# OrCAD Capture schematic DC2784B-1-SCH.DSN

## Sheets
1 PAGE6: size C
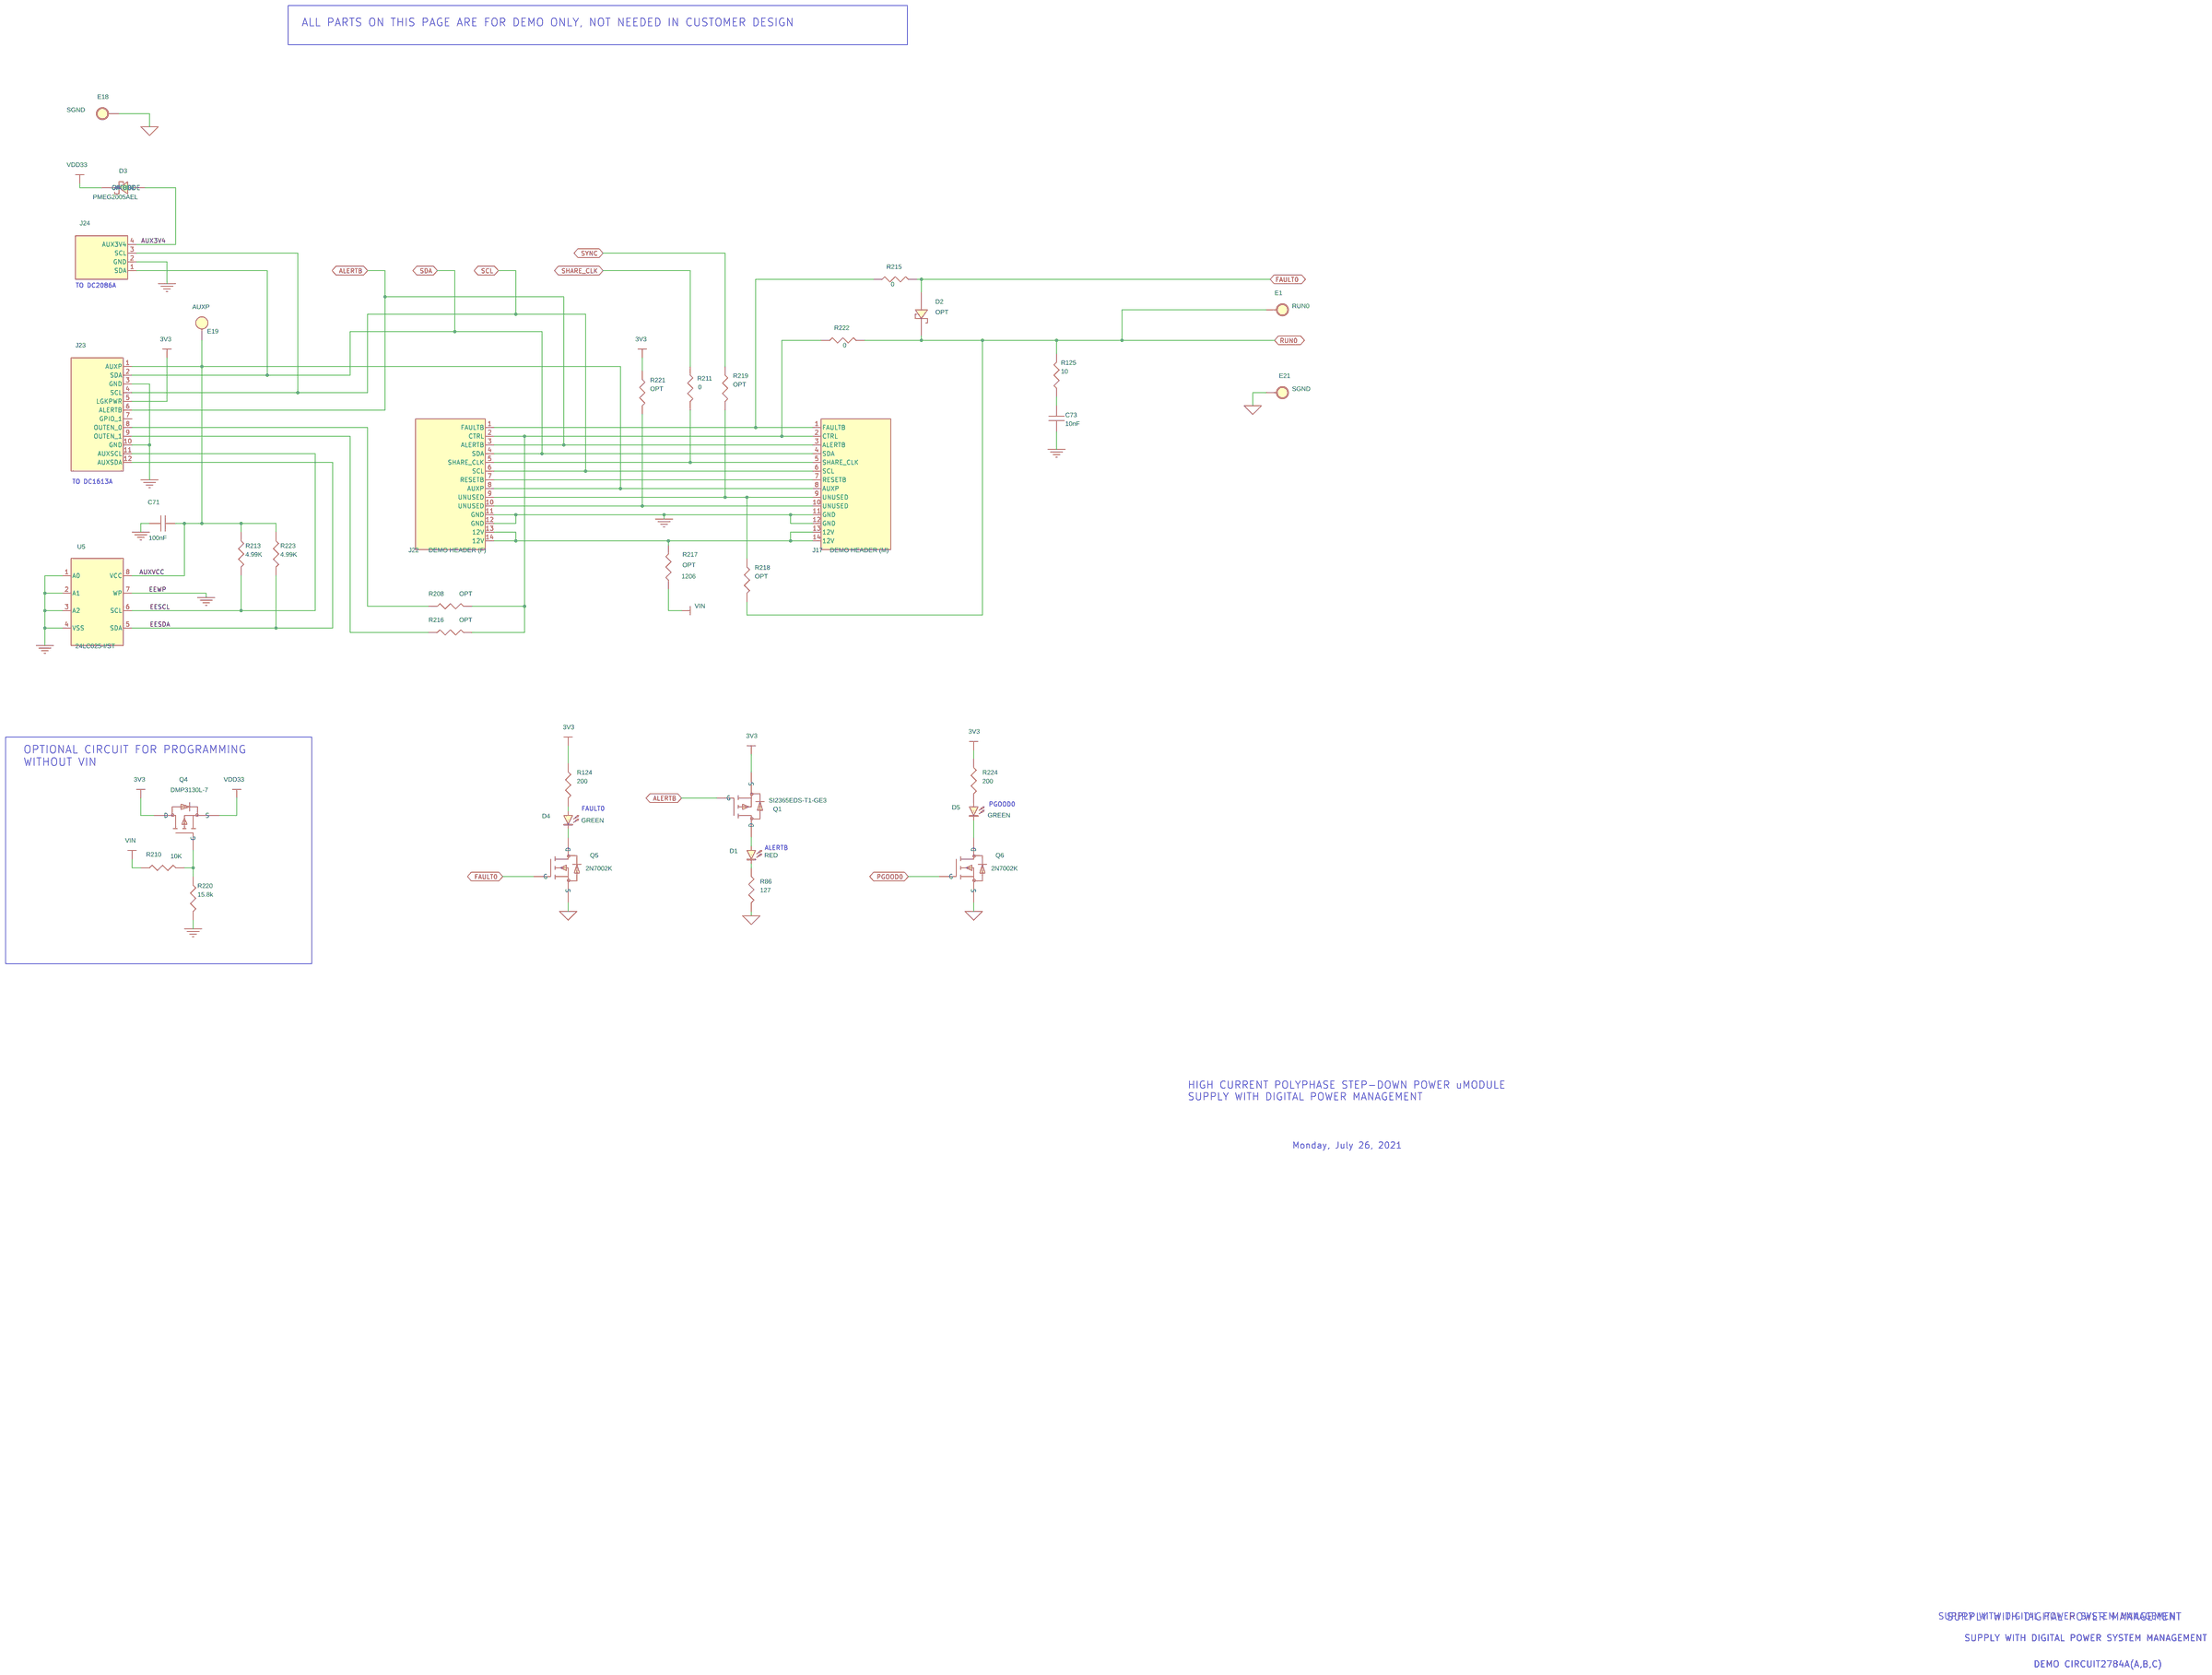
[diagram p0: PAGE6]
2 PAGE5: size B
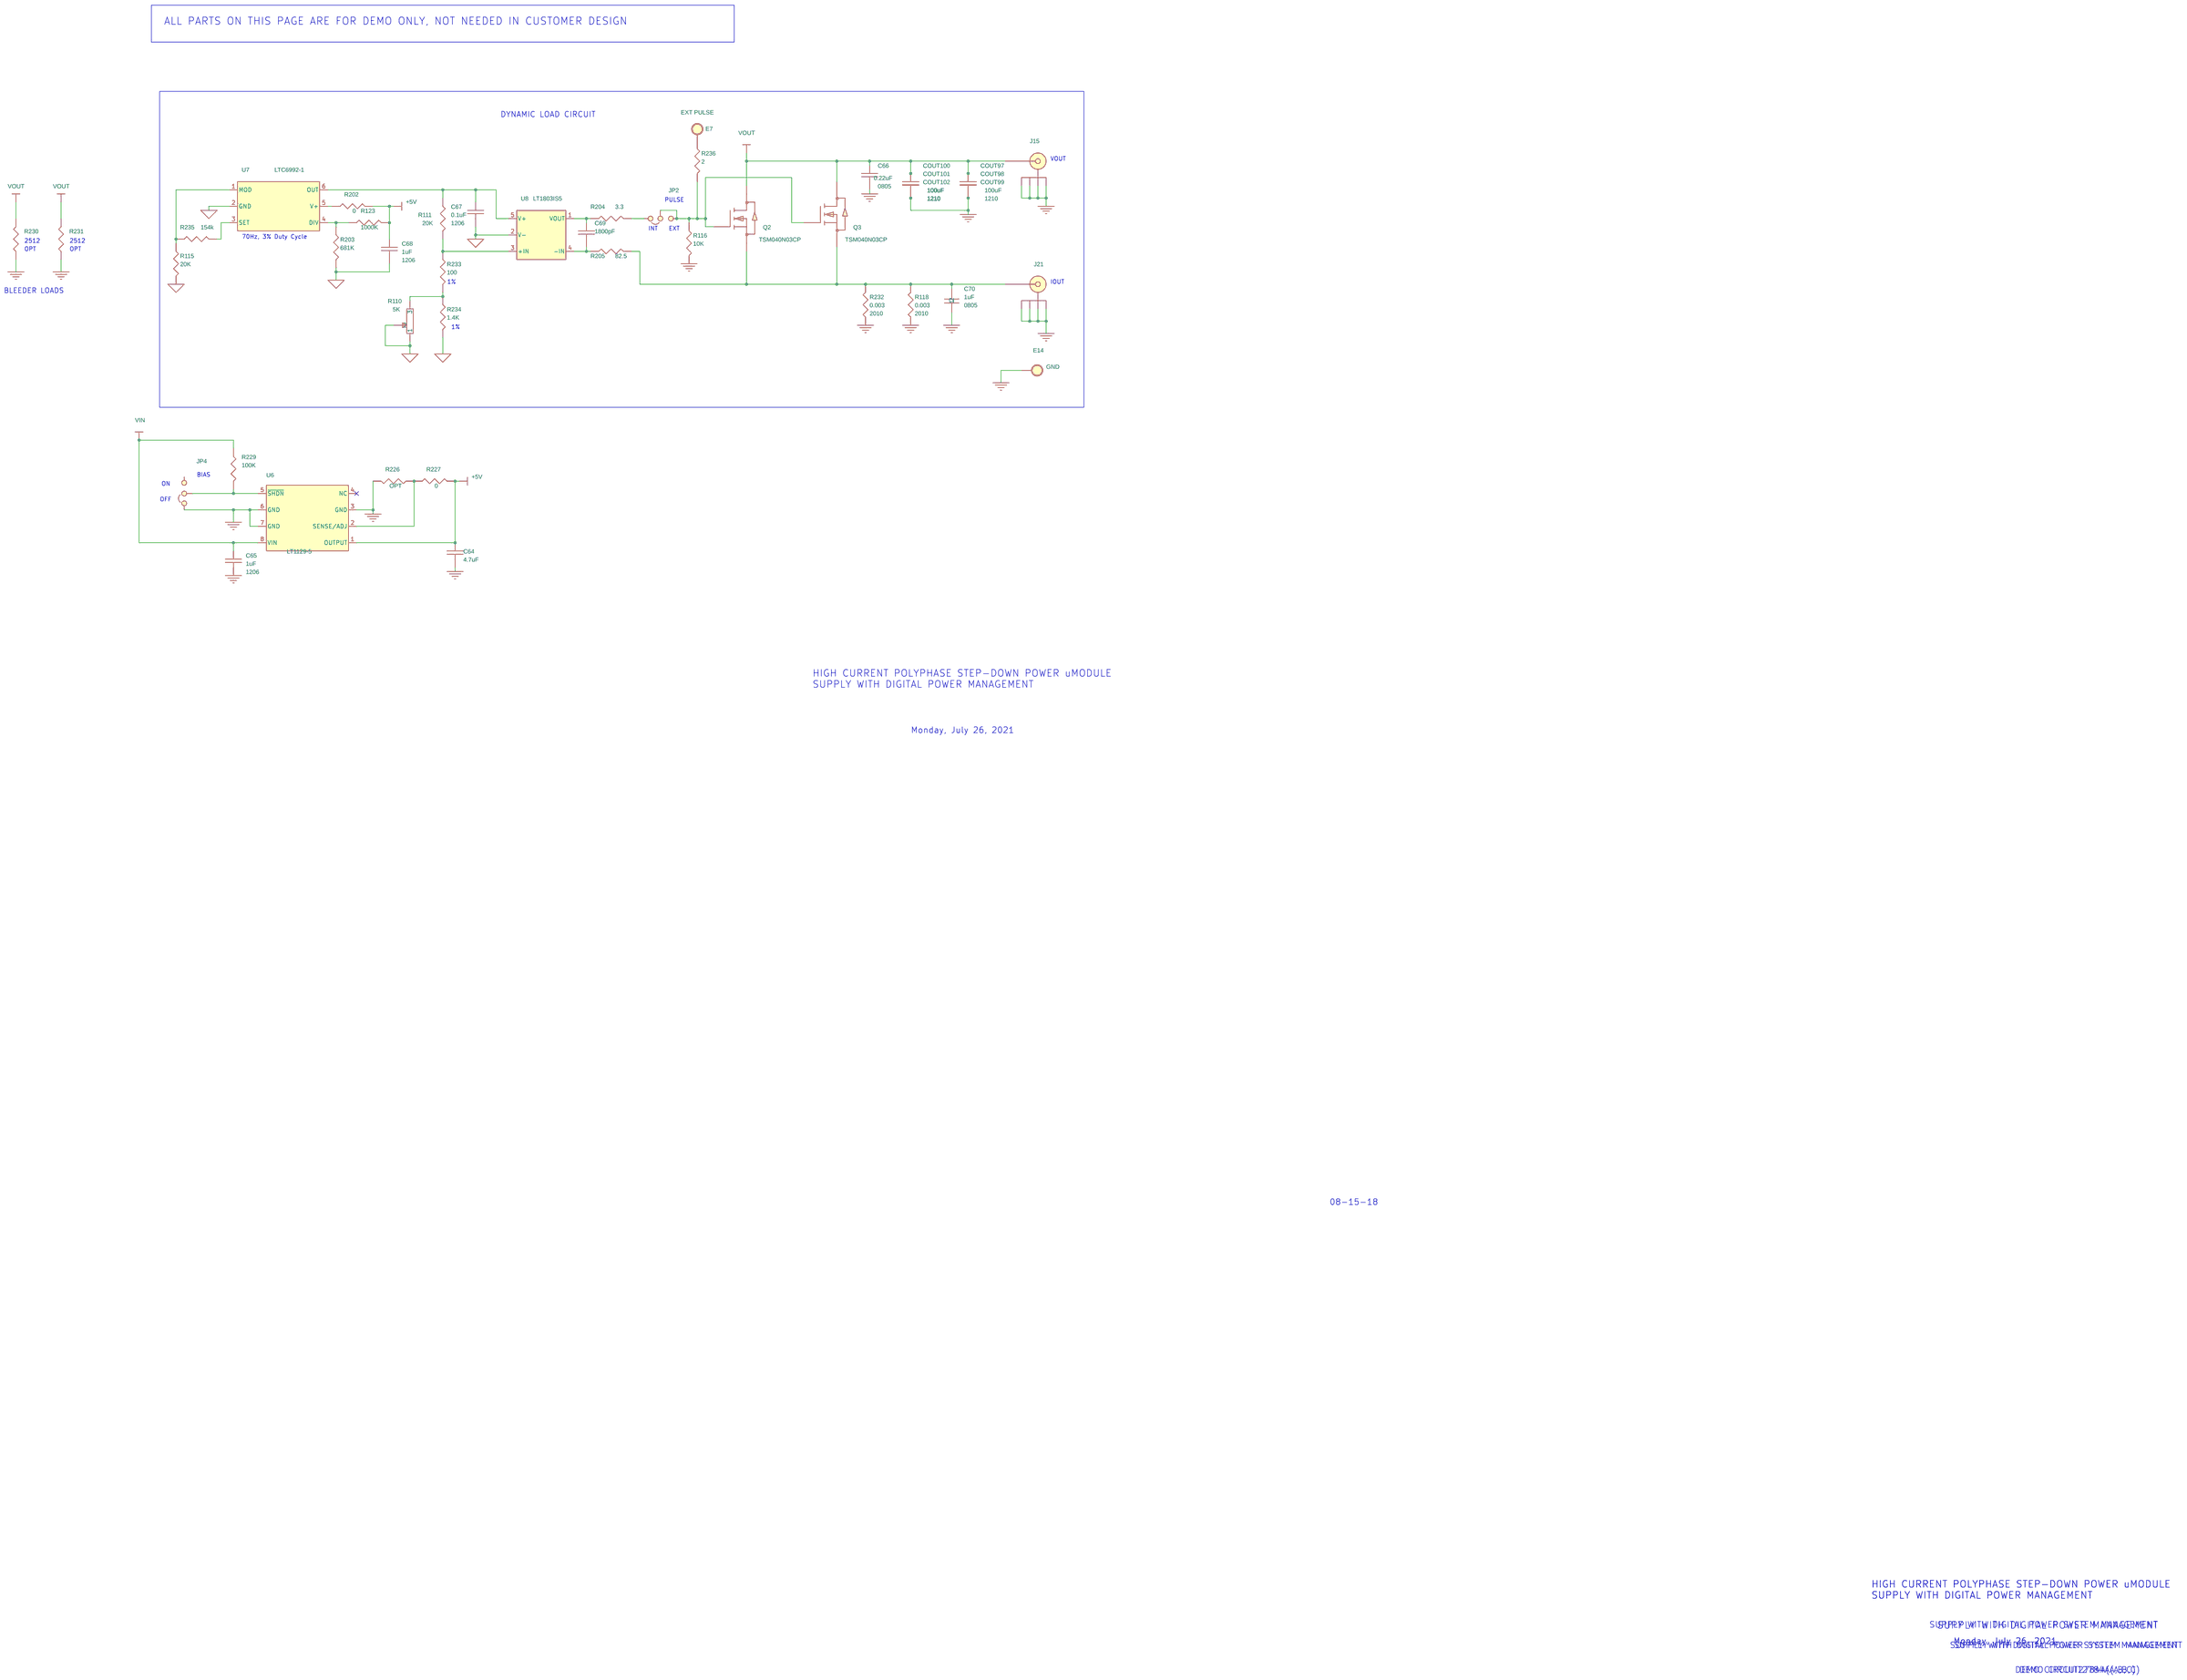
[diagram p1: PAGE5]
3 PAGE4: size Custom
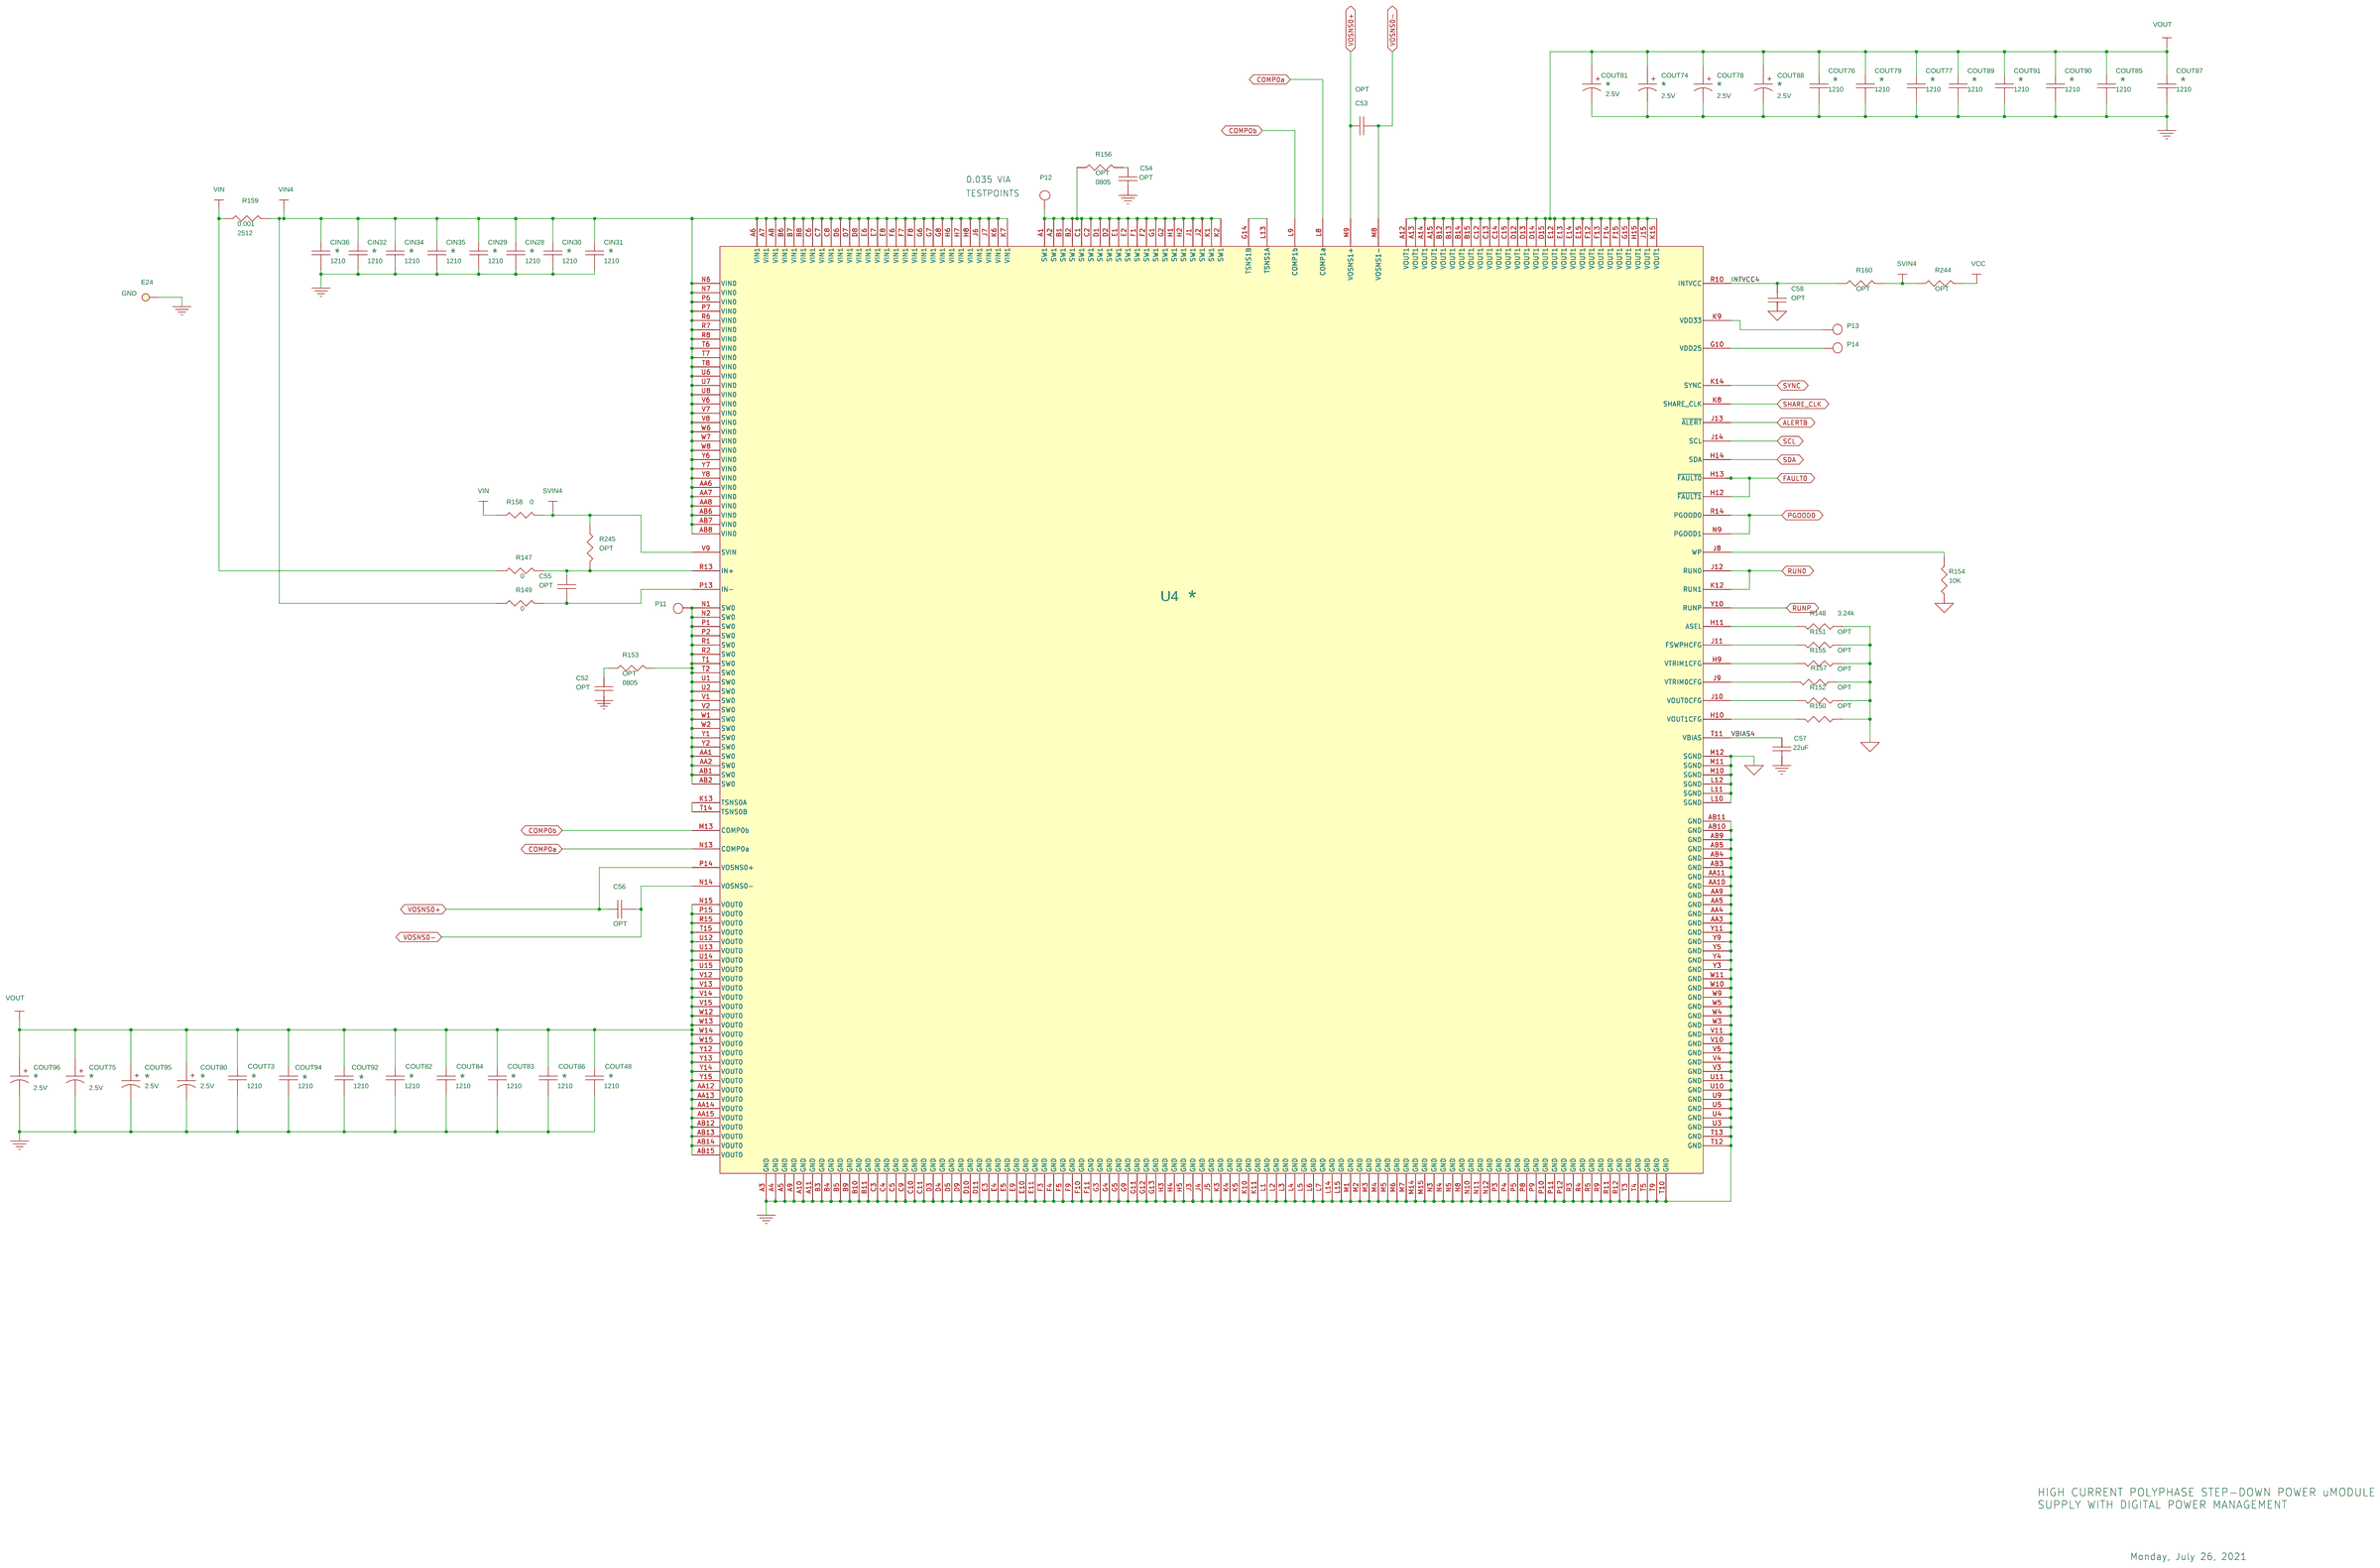
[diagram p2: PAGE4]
4 PAGE3: size Custom
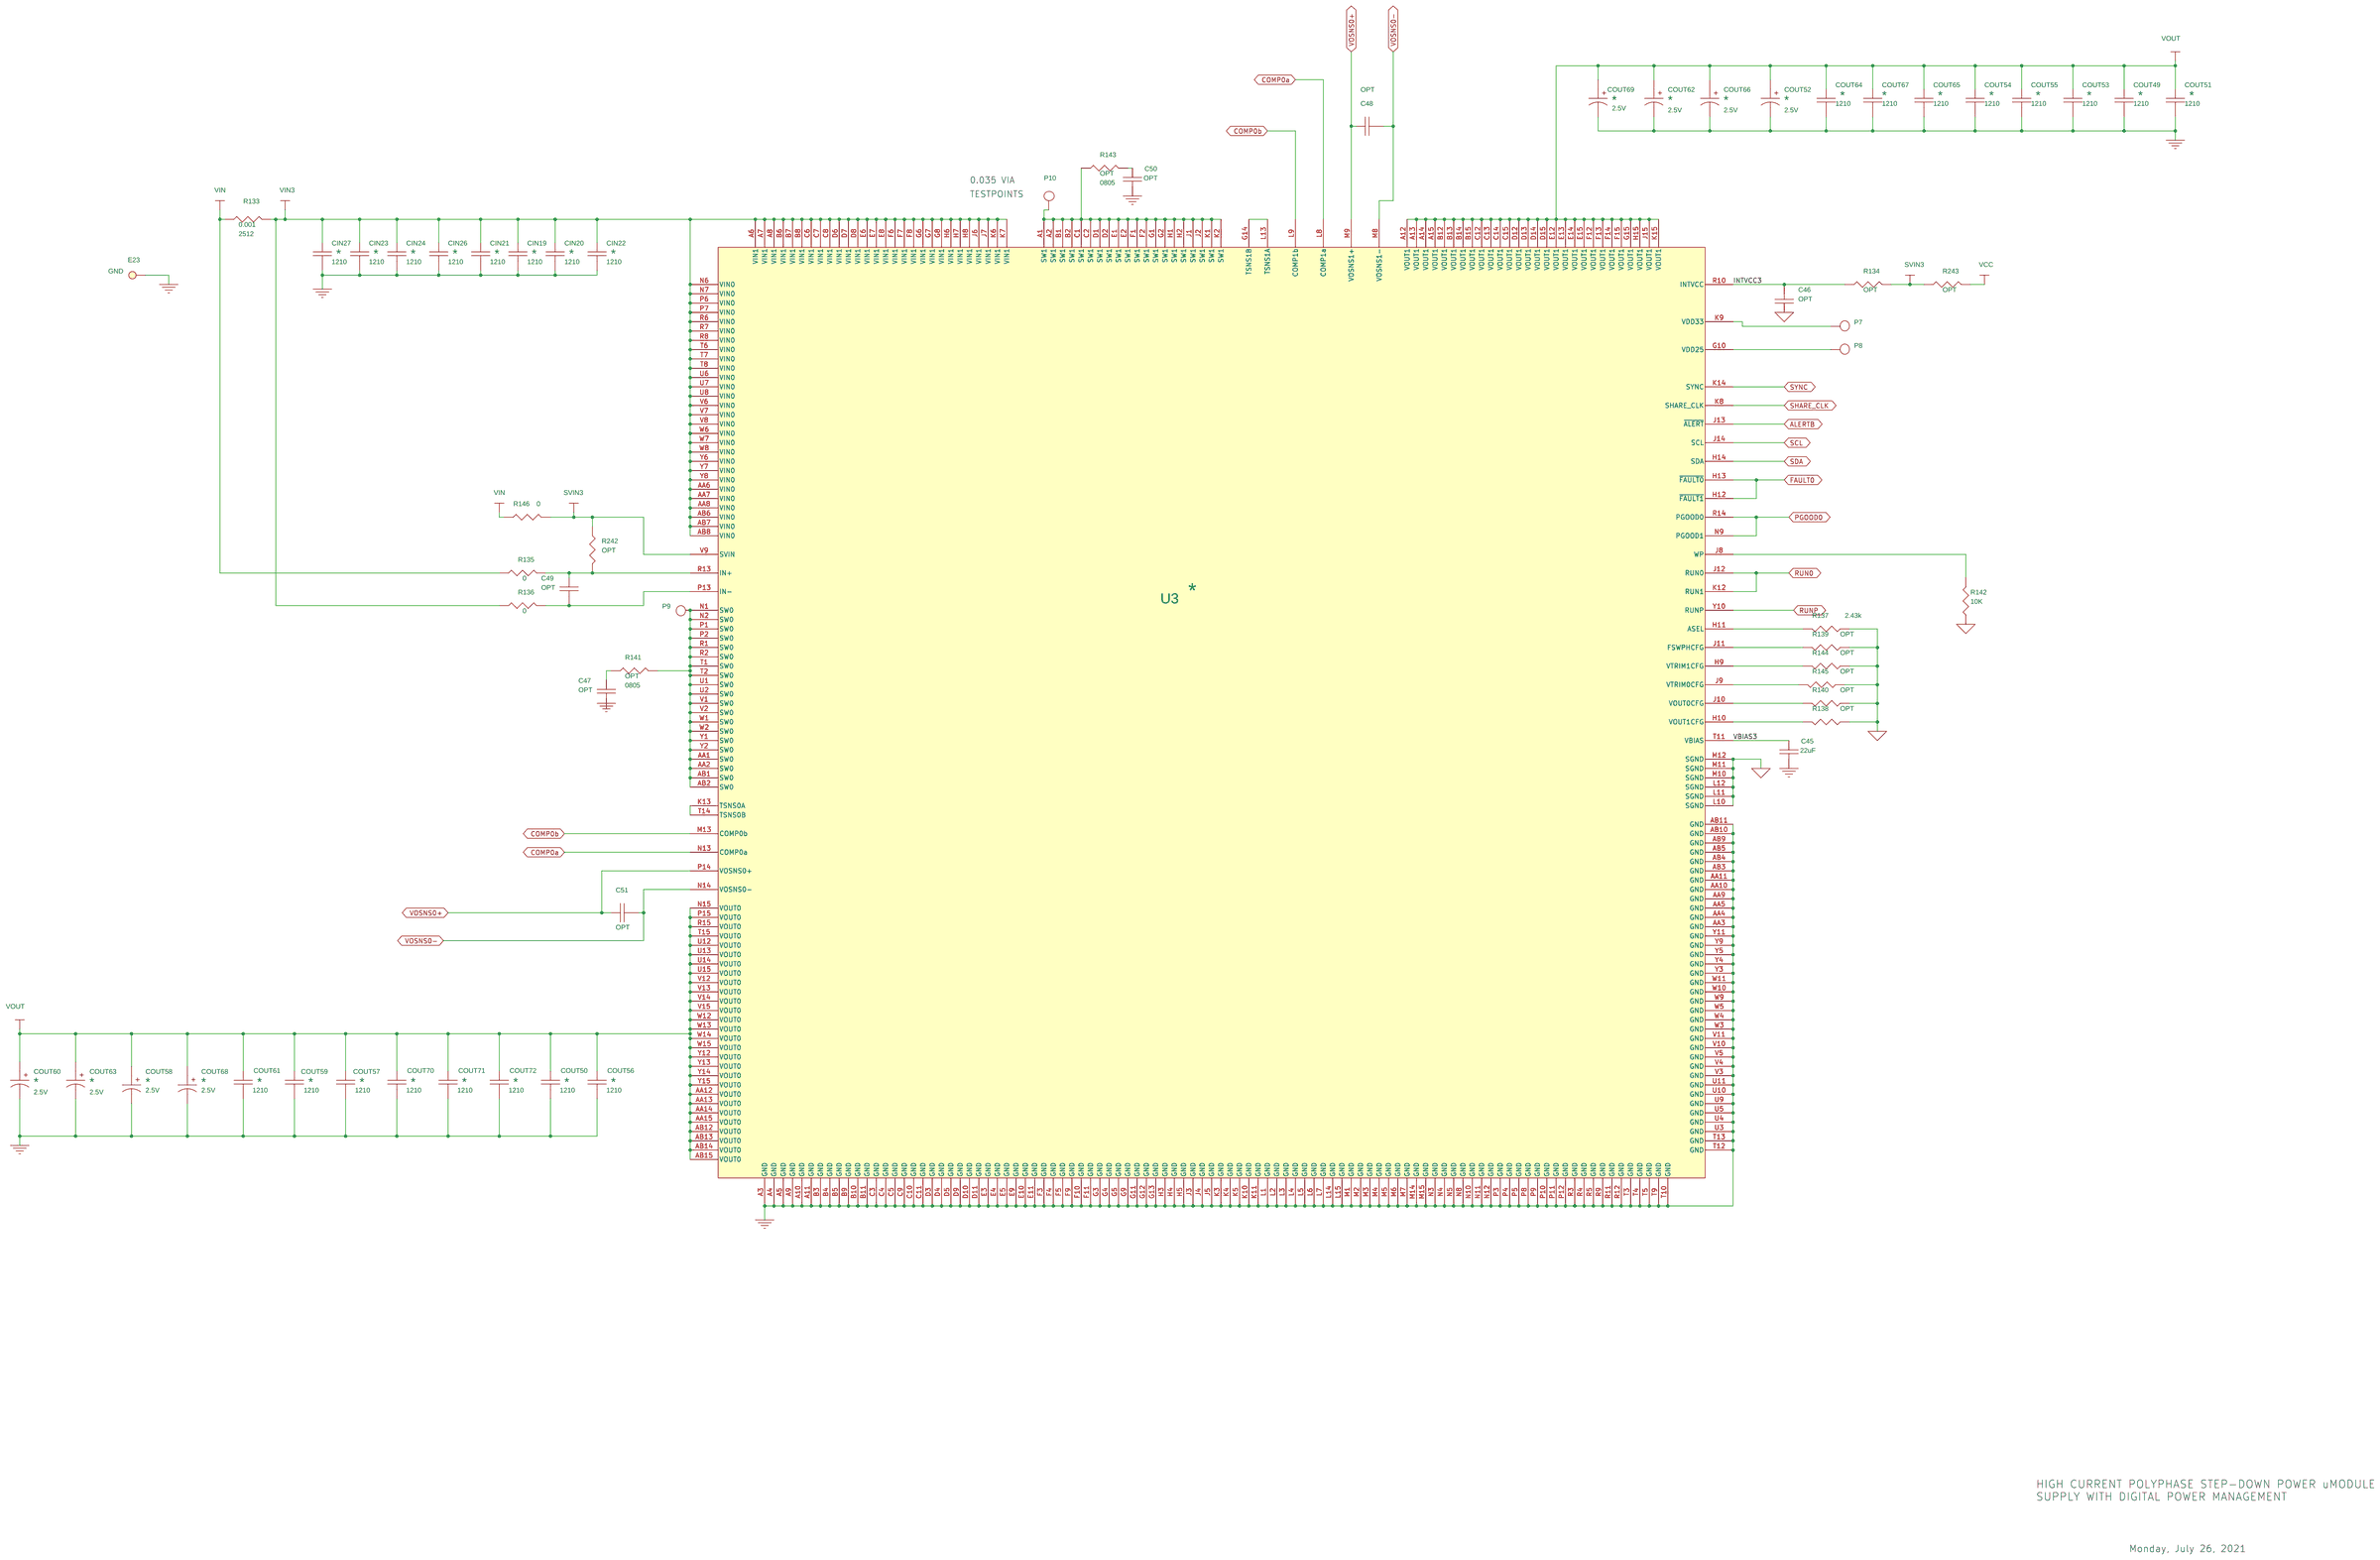
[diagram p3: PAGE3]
5 PAGE2: size Custom
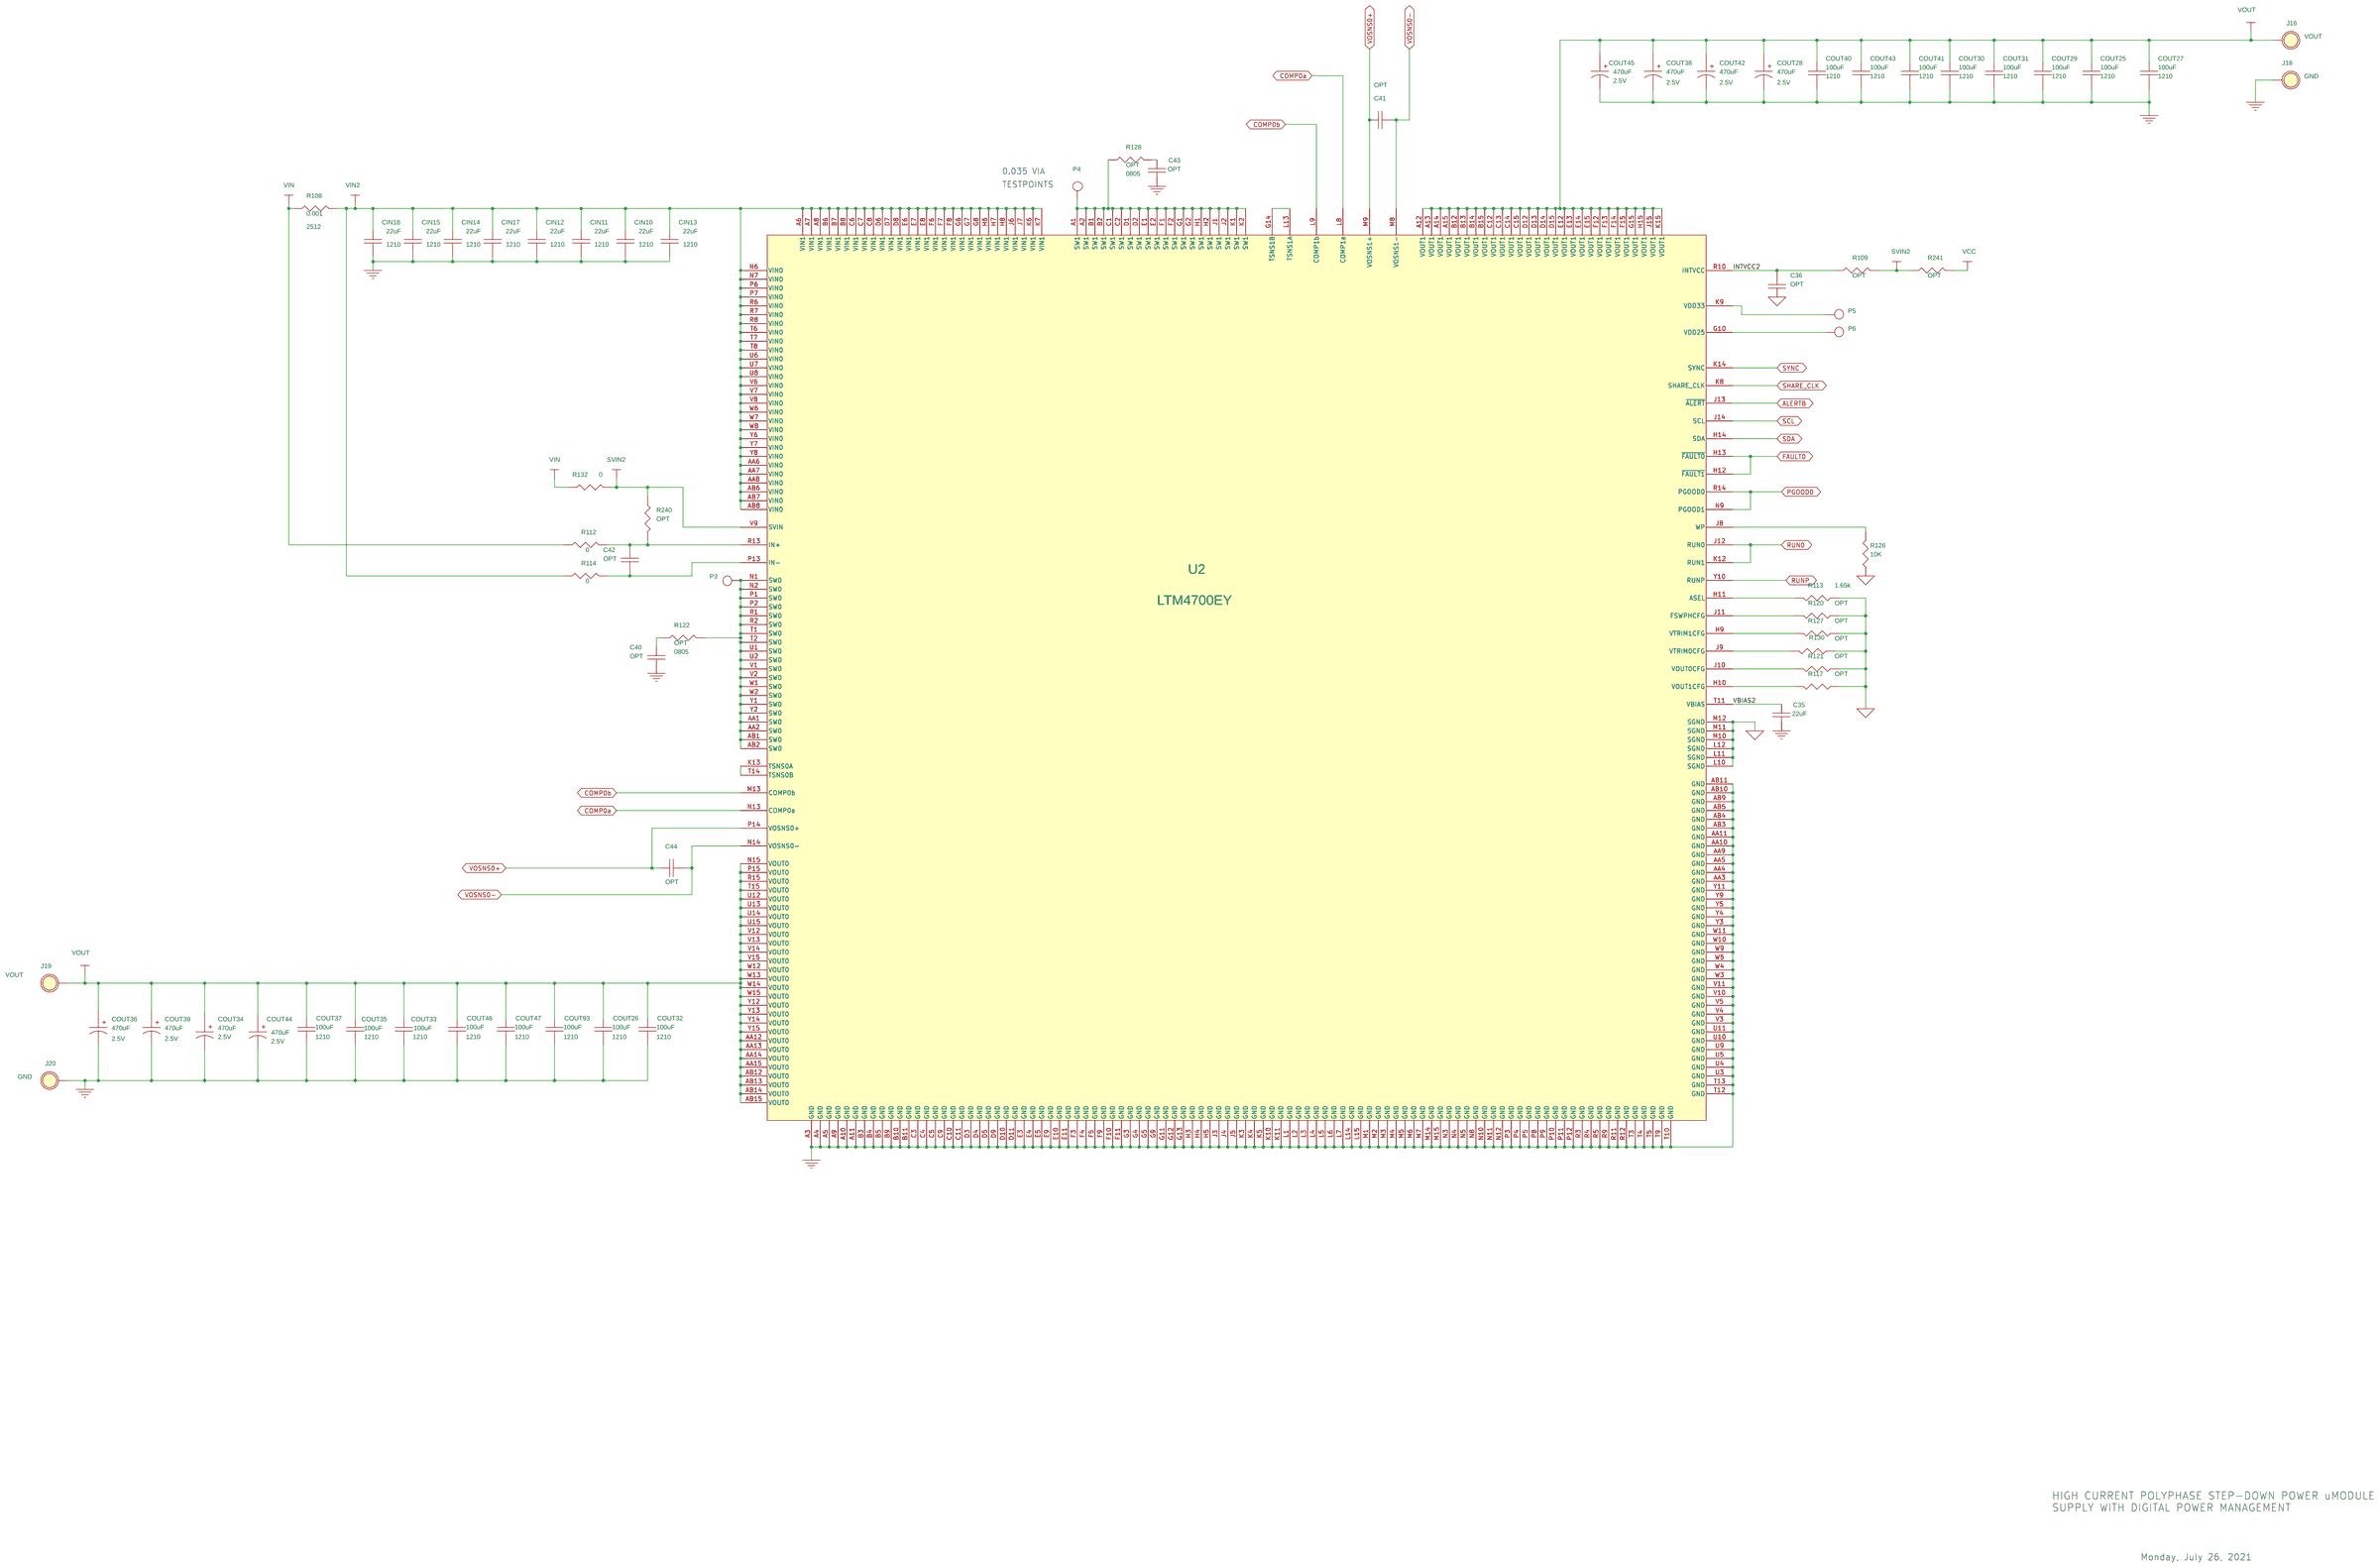
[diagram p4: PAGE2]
6 PAGE1: size Custom
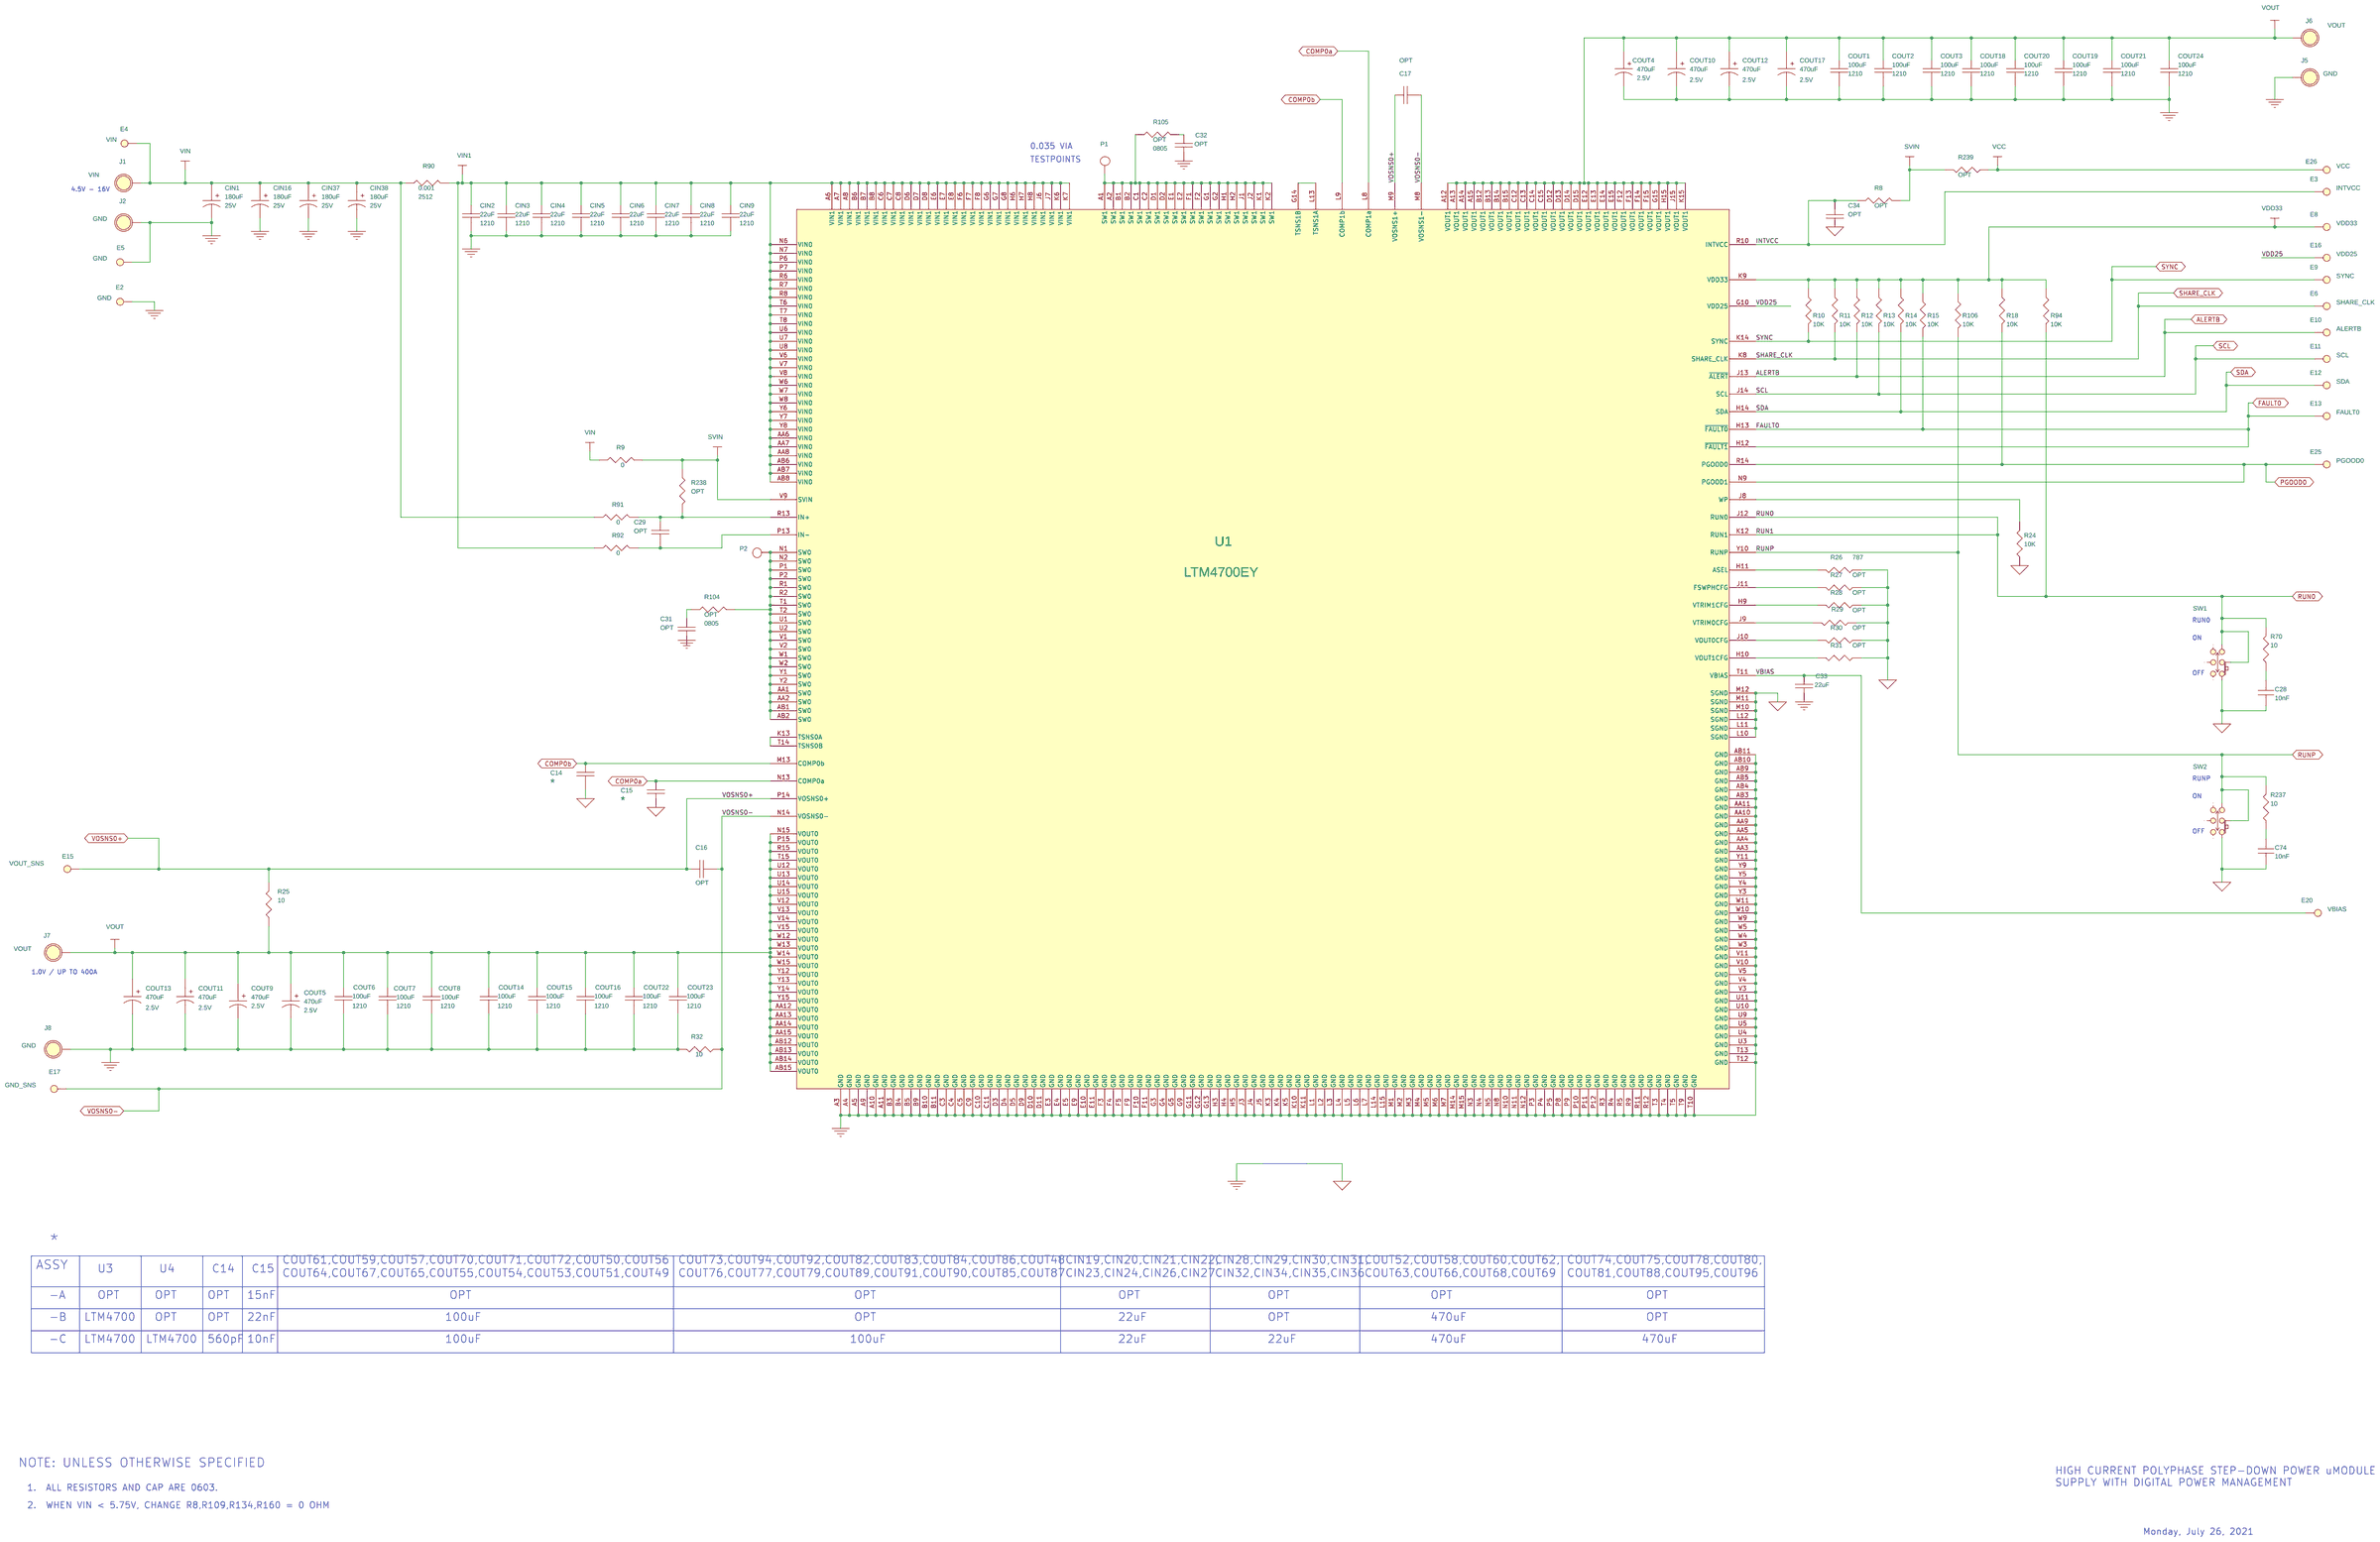
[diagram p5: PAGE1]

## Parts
sheet PAGE1
C14  *  [0603XS]
C15  *  [0603XS]
C16  OPT  [0603]
C17  OPT  [0603]
C28  10nF  [0603]
C29  OPT  [0603XS]
C31  OPT  [0603]
C32  OPT  [0603]
C33  22uF  [0603XS]
C34  OPT  [0603]
C74  10nF  [0603]
CIN1  180uF  [SANYO\8X10]
CIN2  22uF  [1210]
CIN3  22uF  [1210]
CIN4  22uF  [1210]
CIN5  22uF  [1210]
CIN6  22uF  [1210]
CIN7  22uF  [1210]
CIN8  22uF  [1210]
CIN9  22uF  [1210]
CIN16  180uF  [SANYO\8X10]
CIN37  180uF  [SANYO\8X10]
CIN38  180uF  [SANYO\8X10]
COUT1  100uF  [1210]
COUT2  100uF  [1210]
COUT3  100uF  [1210]
COUT4  470uF  [D3L]
COUT5  470uF  [D3L]
COUT6  100uF  [1210]
COUT7  100uF  [1210]
COUT8  100uF  [1210]
COUT9  470uF  [D3L]
COUT10  470uF  [D3L]
COUT11  470uF  [D3L]
COUT12  470uF  [D3L]
COUT13  470uF  [D3L]
COUT14  100uF  [1210]
COUT15  100uF  [1210]
COUT16  100uF  [1210]
COUT17  470uF  [D3L]
COUT18  100uF  [1210]
COUT19  100uF  [1210]
COUT20  100uF  [1210]
COUT21  100uF  [1210]
COUT22  100uF  [1210]
COUT23  100uF  [1210]
COUT24  100uF  [1210]
E2  GND  [TURRETS]
E3  INTVCC  [TURRETS]
E4  TURRETS  [TURRETS]
E5  GND  [TURRETS]
E6  TURRETS  [TURRETS]
E8  VDD33  [TURRETS]
E9  TURRETS  [TURRETS]
E10  TURRETS  [TURRETS]
E11  TURRETS  [TURRETS]
E12  TURRETS  [TURRETS]
E13  TURRETS  [TURRETS]
E15  TURRETS  [TURRETS]
E16  VDD25  [TURRETS]
E17  TURRETS  [TURRETS]
E20  VBIAS  [TURRETS]
E25  TURRETS  [TURRETS]
E26  VCC  [TURRETS]
J1  BANANA SMALL  [CON\LUG\10]
J2  BANANA SMALL  [CON\LUG\10]
J5  BANANA SMALL  [CON\LUG\10]
J6  BANANA SMALL  [CON\LUG\10]
J7  BANANA SMALL  [CON\LUG\10]
J8  BANANA SMALL  [CON\LUG\10]
P1  TURRETS  [PAD]
P2  TURRETS  [PAD]
R8  OPT  [0603XS]
R9  0  [0603XS]
R10  10K  [0603]
R11  10K  [0603]
R12  10K  [0603]
R13  10K  [0603]
R14  10K  [0603]
R15  10K  [0603]
R18  10K  [0603]
R24  10K  [0603]
R25  10  [0603]
R26  787  [0603]
R27  OPT  [0603]
R28  OPT  [0603]
R29  OPT  [0603]
R30  OPT  [0603]
R31  OPT  [0603]
R32  10  [0603]
R70  10  [0603]
R90  0.001  [2512_SENSE]
R91  0  [0603XS]
R92  0  [0603XS]
R94  10K  [0603]
R104  OPT  [0805]
R105  OPT  [0805]
R106  10K  [0603]
R237  10  [0603]
R238  OPT  [0603XS]
R239  OPT  [0603XS]
SW1  JS202011  [JS202011]
SW2  JS202011  [JS202011]
U1  LTM4700EY  [LTC-BGA-330-1568]
sheet PAGE2
C35  22uF  [0603XS]
C36  OPT  [0603]
C40  OPT  [0603]
C41  OPT  [0603]
C42  OPT  [0603XS]
C43  OPT  [0603]
C44  OPT  [0603]
CIN10  22uF  [1210]
CIN11  22uF  [1210]
CIN12  22uF  [1210]
CIN13  22uF  [1210]
CIN14  22uF  [1210]
CIN15  22uF  [1210]
CIN17  22uF  [1210]
CIN18  22uF  [1210]
COUT25  100uF  [1210]
COUT26  100uF  [1210]
COUT27  100uF  [1210]
COUT28  470uF  [D3L]
COUT29  100uF  [1210]
COUT30  100uF  [1210]
COUT31  100uF  [1210]
COUT32  100uF  [1210]
COUT33  100uF  [1210]
COUT34  470uF  [D3L]
COUT35  100uF  [1210]
COUT36  470uF  [D3L]
COUT37  100uF  [1210]
COUT38  470uF  [D3L]
COUT39  470uF  [D3L]
COUT40  100uF  [1210]
COUT41  100uF  [1210]
COUT42  470uF  [D3L]
COUT43  100uF  [1210]
COUT44  470uF  [D3L]
COUT45  470uF  [D3L]
COUT46  100uF  [1210]
COUT47  100uF  [1210]
COUT93  100uF  [1210]
J16  BANANA SMALL  [CON\LUG\10]
J18  BANANA SMALL  [CON\LUG\10]
J19  BANANA SMALL  [CON\LUG\10]
J20  BANANA SMALL  [CON\LUG\10]
P3  TURRETS  [PAD]
P4  TURRETS  [PAD]
P5  TURRETS  [PAD]
P6  TURRETS  [PAD]
R108  0.001  [2512_SENSE]
R109  OPT  [0603XS]
R112  0  [0603XS]
R113  1.65k  [0603]
R114  0  [0603XS]
R117  OPT  [0603]
R120  OPT  [0603]
R121  OPT  [0603]
R122  OPT  [0805]
R126  10K  [0603]
R127  OPT  [0603]
R128  OPT  [0805]
R130  OPT  [0603]
R132  0  [0603XS]
R240  OPT  [0603XS]
R241  OPT  [0603XS]
U2  LTM4700EY  [LTC-BGA-330-1568]
sheet PAGE3
C45  22uF  [0603XS]
C46  OPT  [0603]
C47  OPT  [0603]
C48  OPT  [0603]
C49  OPT  [0603XS]
C50  OPT  [0603]
C51  OPT  [0603]
CIN19  *  [1210]
CIN20  *  [1210]
CIN21  *  [1210]
CIN22  *  [1210]
CIN23  *  [1210]
CIN24  *  [1210]
CIN26  *  [1210]
CIN27  *  [1210]
COUT49  *  [1210]
COUT50  *  [1210]
COUT51  *  [1210]
COUT52  *  [D3L]
COUT53  *  [1210]
COUT54  *  [1210]
COUT55  *  [1210]
COUT56  *  [1210]
COUT57  *  [1210]
COUT58  *  [D3L]
COUT59  *  [1210]
COUT60  *  [D3L]
COUT61  *  [1210]
COUT62  *  [D3L]
COUT63  *  [D3L]
COUT64  *  [1210]
COUT65  *  [1210]
COUT66  *  [D3L]
COUT67  *  [1210]
COUT68  *  [D3L]
COUT69  *  [D3L]
COUT70  *  [1210]
COUT71  *  [1210]
COUT72  *  [1210]
E23  GND  [TURRETS]
P7  TURRETS  [PAD]
P8  TURRETS  [PAD]
P9  TURRETS  [PAD]
P10  TURRETS  [PAD]
R133  0.001  [2512_SENSE]
R134  OPT  [0603XS]
R135  0  [0603XS]
R136  0  [0603XS]
R137  2.43k  [0603]
R138  OPT  [0603]
R139  OPT  [0603]
R140  OPT  [0603]
R141  OPT  [0805]
R142  10K  [0603]
R143  OPT  [0805]
R144  OPT  [0603]
R145  OPT  [0603]
R146  0  [0603XS]
R242  OPT  [0603XS]
R243  OPT  [0603XS]
U3  *  [LTC-BGA-330-1568]
sheet PAGE4
C52  OPT  [0603]
C53  OPT  [0603]
C54  OPT  [0603]
C55  OPT  [0603XS]
C56  OPT  [0603]
C57  22uF  [0603XS]
C58  OPT  [0603]
CIN28  *  [1210]
CIN29  *  [1210]
CIN30  *  [1210]
CIN31  *  [1210]
CIN32  *  [1210]
CIN34  *  [1210]
CIN35  *  [1210]
CIN36  *  [1210]
COUT48  *  [1210]
COUT73  *  [1210]
COUT74  *  [D3L]
COUT75  *  [D3L]
COUT76  *  [1210]
COUT77  *  [1210]
COUT78  *  [D3L]
COUT79  *  [1210]
COUT80  *  [D3L]
COUT81  *  [D3L]
COUT82  *  [1210]
COUT83  *  [1210]
COUT84  *  [1210]
COUT85  *  [1210]
COUT86  *  [1210]
COUT87  *  [1210]
COUT88  *  [D3L]
COUT89  *  [1210]
COUT90  *  [1210]
COUT91  *  [1210]
COUT92  *  [1210]
COUT94  *  [1210]
COUT95  *  [D3L]
COUT96  *  [D3L]
E24  GND  [TURRETS]
P11  TURRETS  [PAD]
P12  TURRETS  [PAD]
P13  TURRETS  [PAD]
P14  TURRETS  [PAD]
R147  0  [0603XS]
R148  3.24k  [0603]
R149  0  [0603XS]
R150  OPT  [0603]
R151  OPT  [0603]
R152  OPT  [0603]
R153  OPT  [0805]
R154  10K  [0603]
R155  OPT  [0603]
R156  OPT  [0805]
R157  OPT  [0603]
R158  0  [0603XS]
R159  0.001  [2512_SENSE]
R160  OPT  [0603XS]
R244  OPT  [0603XS]
R245  OPT  [0603XS]
U4  *  [LTC-BGA-330-1568]
sheet PAGE5
C64  4.7uF  [0603]
C65  1uF  [1206]
C66  0.22uF  [0805]
C67  0.1uF  [1206]
C68  1uF  [1206]
C69  1800pF  [0603]
C70  1uF  [0805]
COUT97  100uF  [1210]
COUT98  100uF  [1210]
COUT99  100uF  [1210]
COUT100  100uF  [1210]
COUT101  100uF  [1210]
COUT102  100uF  [1210]
E7  TURRETS  [TURRETS]
E14  TURRETS  [TURRETS]
J15  XXX  [BNC]
J21  XXX  [BNC]
JP2  JP3X1/079\NO\12  [HD1X3-079]
JP4  JP3X1/079\NO\12  [HD1X3-079]
Q2  TSM040N03CP  [TO-252]
Q3  TSM040N03CP  [TO-252]
R110  5K  [POTENTIOMETER/3386]
R111  20K  [0603]
R115  20K  [0603]
R116  10K  [0603]
R118  0.003  [2010]
R123  1000K  [0603]
R202  0  [0603]
R203  681K  [0603]
R204  3.3  [0603]
R205  82.5  [0603]
R226  OPT  [0603]
R227  0  [0603]
R229  100K  [0603]
R230  OPT  [2512SENSE]
R231  OPT  [2512SENSE]
R232  0.003  [2010]
R233  100  [0603]
R234  1.4K  [0603]
R235  154k  [0603]
R236  2  [0603]
U6  LT1129-5  [SO8NB]
U7  LTC6992-1  [S6-TSOT23]
U8  LT1803IS5  [S5-TSOT23]
sheet PAGE6
C71  100nF  [0603]
C73  10nF  [0603]
D1  RED  [led]
D2  OPT  [SOD323]
D3  PMEG2005AEL  [PMEG2005AEL]
D4  GREEN  [led]
D5  GREEN  [led]
E1  TURRETS  [TURRETS]
E18  SGND  [TURRETS]
E19  AUXP  [TURRETS]
E21  SGND  [TURRETS]
J17  DEMO HEADER (M)  [NPPN072FJFN]
J22  DEMO HEADER (F)  [NPPN072FJFN-RC]
J23  HD2X6-079  [HD2X6-079-MOLEX]
J24  HD2X6-079-PMBUS_0  [DF3A-4P-2DSA]
Q1  SI2365EDS-T1-GE3  [SOT-23]
Q4  DMP3130L-7  [SOT-23]
Q5  2N7002K  [SOT-23]
Q6  2N7002K  [SOT-23]
R86  127  [0603]
R124  200  [0603]
R125  10  [0603]
R208  OPT  [0603]
R210  10K  [0603]
R211  0  [0603]
R213  4.99K  [0603]
R215  0  [0603]
R216  OPT  [0603]
R217  OPT  [1206]
R218  OPT  [0603]
R219  OPT  [0603]
R220  15.8k  [0603]
R221  OPT  [0603]
R222  0  [0603]
R223  4.99K  [0603]
R224  200  [0603]
U5  24LC025-I/ST  [TSSOP-8_4.4MM]

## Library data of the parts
C14-C17 C29 C31-C36 C40-C58 = CAP0603_1: Component: cap; Manufacturer: TDK; Manufacturer P/N: C1608C0G1H102J; Tolerance: 5%; Type: cer 0603; Vendor: Digikey; Vendor P/N: 445-1293-1-ND; Volts/Amps/Watts: 50V
C28 C73 C74 = CAP_NP: CAP, 0603 10nF 10% 25V X7R; Part Number: AVX 06033C103KAT2A
CIN1 CIN16 CIN37 CIN38 = CAPR12X5_0: Component: cap; Manufacturer: SANYO; Tolerance: 20%; Type: OS-CON; Volts/Amps/Watts: 25V
CIN2-CIN15 CIN17-CIN24 CIN26-CIN32 CIN34-CIN36 = CAP1210_1: Component: cap; Manufacturer: Taiyo Yuden; Manufacturer P/N: GMK325BJ106KN-T; Tolerance: 10%; Type: cer 1210; Vendor: Digikey; Vendor P/N: 587-1439-1-ND; Volts/Amps/Watts: 35V
COUT1 COUT30 COUT40 COUT54 COUT64 COUT76 COUT89 = CAP0603_1: Component: cap; Manufacturer: TDK; Manufacturer P/N: C3225X5R0J107M; Tolerance: 20%; Type: cer 1210 X5R; Vendor: Digikey; Vendor P/N: 445-1437-1-ND; Volts/Amps/Watts: 6.3v
COUT2 COUT3 COUT19-COUT21 COUT24 = CAP0603_1: Component: cap; Manufacturer: TDK; Part Type: CAP1210; Tolerance: 20%; Type: cer 1210 X5R; Vendor: Digikey; Vendor P/N: 445-1437-1-ND; Volts/Amps/Watts: 6.3v
COUT4 COUT5 COUT9-COUT13 COUT17 = CAPR12X5_0: Component: cap; Manufacturer: SANYO; Tolerance: 20%; Type: SP-CAP; Volts/Amps/Watts: 2.5V
COUT6-COUT8 COUT14-COUT16 COUT22 COUT23 COUT25-COUT27 COUT29 COUT31-COUT33 COUT35 COUT37 COUT41 COUT43 COUT46-COUT51 COUT53 COUT55-COUT57 COUT59 COUT61 COUT65 COUT67 COUT70-COUT73 COUT77 COUT79 COUT82-COUT87 COUT90-COUT94 COUT97-COUT102 = CAP0603_1: Component: cap; Manufacturer: TDK; Manufacturer P/N: C3225X5R0J107M; Part Type: CAP1210; Tolerance: 20%; Type: cer 1210 X5R; Vendor: Digikey; Vendor P/N: 445-1437-1-ND; Volts/Amps/Watts: 6.3v
COUT18 = CAP0603_1: Component: cap; Manufacturer: TDK; Tolerance: 20%; Type: cer 1210 X5R; Vendor: Digikey; Vendor P/N: 445-1437-1-ND; Volts/Amps/Watts: 6.3v
E2 E5 E23 E24 = TURRETS_1: Component: tp; Manufacturer: Keystone; Manufacturer P/N: 1593-2; Vendor: Digikey; Vendor P/N: 1593-2K-ND
E3 E8 E16 E20 E26 = TURRETS_1: Component: tp; Label: GND; Manufacturer: Keystone; Manufacturer P/N: 1593-2; Vendor: Digikey; Vendor P/N: 1593-2K-ND
E4 = TURRETS_1: Component: tp; Label: VIN; Manufacturer: Keystone; Manufacturer P/N: 1593-2; Vendor: Digikey; Vendor P/N: 1593-2K-ND
E6 = TURRETS_1: Component: tp; Label: SHARE_CLK; Manufacturer: Keystone; Manufacturer P/N: 1593-2; Vendor: Digikey; Vendor P/N: 1593-2K-ND
E9 = TURRETS_1: Component: tp; Label: SYNC; Manufacturer: Keystone; Manufacturer P/N: 1593-2; Vendor: Digikey; Vendor P/N: 1593-2K-ND
E10 = TURRETS_1: Component: tp; Label: ALERTB; Manufacturer: Keystone; Manufacturer P/N: 1593-2; Vendor: Digikey; Vendor P/N: 1593-2K-ND
E11 = TURRETS_1: Component: tp; Label: SCL; Manufacturer: Keystone; Manufacturer P/N: 1593-2; Vendor: Digikey; Vendor P/N: 1593-2K-ND
E12 = TURRETS_1: Component: tp; Label: SDA; Manufacturer: Keystone; Manufacturer P/N: 1593-2; Vendor: Digikey; Vendor P/N: 1593-2K-ND
E13 = TURRETS_1: Component: tp; Label: FAULT0; Manufacturer: Keystone; Manufacturer P/N: 1593-2; Vendor: Digikey; Vendor P/N: 1593-2K-ND
E15 = TURRETS_1: Component: tp; Label: VOUT_SNS; Vendor: Digikey; Vendor P/N: 1593-2K-ND
E17 = TURRETS_1: Component: tp; Label: GND_SNS; Vendor: Digikey; Vendor P/N: 1593-2K-ND
E25 = TURRETS_1: Component: tp; Label: PGOOD0; Manufacturer: Keystone; Manufacturer P/N: 1593-2; Vendor: Digikey; Vendor P/N: 1593-2K-ND
J1 = BANANA_SMALL_0: Component: conn; Label: VIN
J2 J5 J8 J18 J20 = BANANA_SMALL_0: Component: conn; Label: GND
J6 J7 J16 J19 = BANANA_SMALL_0: Component: conn; Label: VOUT
P1-P14 = PAD_2: Component: tp; Label: <Label>; Vendor: Digikey; Vendor P/N: 1593-2K-ND
R8 R109 R123 R134 R160 R241 R243 R244 = RES0603_9: Label: OPT 0; Manufacturer: Rohm; Manufacturer P/N: RHM0.0GCT-ND; Vendor: Digikey
R9 R132 R146 R158 = RES0603_3
R10-R15 R18 R24 R29 R30 R91 R92 R94 R104-R106 R112 R114 R121 R122 R126 R128 R130 R135 R136 R140-R143 R145 R147 R149 R152-R154 R156 R157 = RES0603_9: Manufacturer: ROHM; Manufacturer P/N: MCR03EZPFX1002; Vendor: Digikey; Vendor P/N: RHM10.0KHCT-ND; Volts/Amps/Watts: 0.1W
R25 = RES0603_9: Manufacturer: Rohm; Manufacturer P/N: MCR03EZPFX1000; Vendor: Digikey; Vendor P/N: RHM100HCT-ND; Volts/Amps/Watts: 0.1W
R26 R27 R113 R120 R137 R139 R148 R151 R238-R240 R242 R245 = RES0603_9: Manufacturer: Panasonic; Manufacturer P/N: ERJ-3EKF2002V; Vendor: Digikey; Vendor P/N: P20.0KHCT-ND; Volts/Amps/Watts: 0.1W
R28 R127 R144 R155 = RES0603_9: Manufacturer: Panasonic; Manufacturer P/N: ERJ-3EKF1000V; Vendor: Digikey; Vendor P/N: P100HCT-ND; Volts/Amps/Watts: 0.1W
R31 R117 R138 R150 = RES0603_9: Manufacturer: Panasonic; Manufacturer P/N: ERJ-3EKF1021V; Vendor: Digikey; Vendor P/N: P1.02KHCT-ND; Volts/Amps/Watts: 0.1W
R32 = RES0603_9: Manufacturer: Yageo; Manufacturer P/N: RC0603JR-070RL; Tolerance: 5%; Vendor: Digikey; Vendor P/N: 311-0.0GRCT-ND; Volts/Amps/Watts: 0.1W
R70 R237 = RES0603_1: RES, 0603 10 OHMS 5% 0.1W; Manufacturer: Rohm; Manufacturer P/N: RHM0.0GCT-ND; Part Number: VISHAY CRCW060310R0JNEA; Tolerance: 5%; Vendor: Digikey; Vendor P/N: RHM0.0GCT-ND; Volts/Amps/Watts: 0.1W
R90 R108 R133 R159 = RES2512_0: Part Type: 2512; Tolerance: <Tolerance>
SW1 SW2 = JP3X1_079_NO_12_3: SWITCH, SUBMINATURE SLIDE; Part Number: C&K JS202011CQN
U1-U4 = LTC3880-M0001_60: Component: IC; Manufacturer: LTC; Manufacturer P/N: LTC3880_M0001; Vendor: LTC; Vendor P/N: LTC3880_M0001
COUT28 COUT34 COUT36 COUT38 COUT39 COUT42 COUT44 COUT45 COUT52 COUT58 COUT60 COUT62 COUT63 COUT66 COUT68 COUT69 COUT74 COUT75 COUT78 COUT80 COUT81 COUT88 COUT95 COUT96 = CAPR12X5_0: Component: cap; Manufacturer: SANYO; Manufacturer P/N: EEFGX0E471R; Tolerance: 20%; Type: SP-CAP; Volts/Amps/Watts: 2.5V
C64 = CAP1206_1: Manufacturer: AVX; Tolerance: 10%; Type: cer 1206 X7R; Vendor: Digikey; Vendor P/N: 478-1567-1-ND; Volts/Amps/Watts: 25V
C65 C67 C68 = CAP1206_1: Manufacturer: AVX; Manufacturer P/N: 12063C105KAT2A; Tolerance: 10%; Type: cer 1206 X7R; Vendor: Digikey; Vendor P/N: 478-1567-1-ND; Volts/Amps/Watts: 25V
C66 = CAP1206_1: Manufacturer: Kemet; Manufacturer P/N: C1206C106K8RACTU; Tolerance: 10%; Type: cer 1206 X7R; Vendor: Digikey; Vendor P/N: 399-4937-1-ND; Volts/Amps/Watts: 10V
C69 = CAP0603_2: Component: cap; Manufacturer: TDK; Manufacturer P/N: C1608C0G1H102J; Tolerance: 5%; Type: cer 0603; Vendor: Digikey
C70 = CAP_NP_1: CAP, 0603 1.5nF 10% 50V X7R; Part Number: AVX 06033C152KAT
E7 = TURRETS_2: Label: EXT PULSE; Manufacturer: Keystone; Manufacturer P/N: 1593-2; Vendor: Digikey; Vendor P/N: 1593-2K-ND
E14 = TURRETS_2: Label: GND; Manufacturer: Keystone; Manufacturer P/N: 1593-2; Vendor: Digikey; Vendor P/N: 1593-2K-ND
J15 J21 = BNC5-SCH_0: CONN,BNC,5 PINS; Part Number: CONNEX 112404
JP2 JP4 = JP3X1_079_NO_12_2
Q2 Q3 = SUND50N03: XSTR, N-CHANNEL DMOS FET; 5TH PART FIELD: 2N7002TA
R110 = POT_A_0
R111 R115 R116 R202-R205 R226 R227 R233-R236 = RES0603_9: Manufacturer: ROHM; Manufacturer P/N: MCR03EZPFX4991; Vendor: Digikey; Vendor P/N: RHM4.99KHCT-ND; Volts/Amps/Watts: 0.1w
R118 R232 = RES0603_5: Label: 1W; Manufacturer: VISHAY; Manufacturer P/N: CRCW251230R0JNEG; Part Type: 2512; Tolerance: 5%; Vendor: Digikey; Vendor P/N: 541-30XCT-ND; Volts/Amps/Watts: 0.1W
R229 = RES0603_11
R230 R231 = RES0603_6: Label: 1W; Tolerance: 5%; Vendor: Digikey; Vendor P/N: 541-30XCT-ND; Volts/Amps/Watts: 0.1W
U6 = LT1129CS8-3.3
U7 = LT1129CS8-3_0.3
U8 = LT1129CS8-3_3.3
C71 = CAP_NP: CAP, 0603 100nF 20% 16V X7R; Part Number: AVX 0603YC104MAT2A
D1 = DIODE-LED_3: Label: GREEN; Manufacturer: PANASONIC
D2 = DIODE_SCHOTTKY_9: DIODE, SCHOTTKY 30V, 100mA; Part Number: CENTRAL SEMI CMDSH-3-TR
D3 = DIODE_SCHOTTKY_0
D4 D5 = DIODE-LED_3: Manufacturer: PANASONIC; Manufacturer P/N: LN1371SGTRP
E1 = TURRETS_2: Component: tp; Label: RUN0; Manufacturer: Keystone; Manufacturer P/N: 1593-2; Vendor: Digikey; Vendor P/N: 1593-2K-ND
E18 E21 = TURRETS_2: Component: tp; Label: GND; Manufacturer: Keystone; Manufacturer P/N: 1593-2; Vendor: Digikey; Vendor P/N: 1593-2K-ND
E19 = E_0: TURRET; Part Number: MILL MAX 2501-2-00-80-00-00-07-0
J17 = PMBUS_CONNECTOR20_3: CONN, SOCKET 20PIN  DUAL ROW R/A; Component: con; Manufacturer: Mill Max; Manufacturer P/N: 803-93-020-20-001; Part Number: MILL MAX 803-93-020-20-001; Type: conn  RA 20 dual row; Vendor: LTC; Vendor P/N: 803-93-020-20-001
J22 = PMBUS_HEADER20_3: HEADER, 20PIN DUAL ROW R/A; Component: con; Manufacturer: Mill Max; Manufacturer P/N: 802-40-020-20-0001; Part Number: MILL MAX 802-40-020-20-0001; Type: header RA 20 dual row; Vendor: LTC; Vendor P/N: 802-40-020-20-001
J23 = HD2X6-079-PMBUS_2: HEADER, 12PIN 2mm STR DL; Label: DC1427A HEADER; Manufacturer: MOLEX; Manufacturer P/N: 87831-1220; Part Number: FCI 98414-G06-12ULF; Type: header 12POS 2MM VERT; Vendor: Digikey; Vendor P/N: WM18561-ND
J24 = HD2X6-079-PMBUS_4: HEADER, 4PIN 2mm STR DL; Manufacturer: Hirose; Type: header 4POS 2MM VERT
Q1 = P-MOSFET: XSTR, N-CHANNEL DMOS FET
Q4 = P-MOSFET: XSTR, N-CHANNEL DMOS FET; Part Number: VISHAY TP0101K-T1-E3
Q5 = TRANSISTOR_0: XSTR, N-CHANNEL DMOS FET
Q6 = TRANSISTOR_1: XSTR, N-CHANNEL DMOS FET
R86 R124 R224 = RES0603_9: Label: OPT 0; Manufacturer: Rohm; Manufacturer P/N: RHM0.0GCT-ND; Tolerance: 5%; Vendor: Digikey; Vendor P/N: RHM0.0GCT-ND; Volts/Amps/Watts: 0.1W
R125 = RES0603_1: RES, 0603 10 OHMS 5% 1/10W; Manufacturer: Rohm; Manufacturer P/N: RHM0.0GCT-ND; Part Number: VISHAY CRCW060310R0JNEA; Tolerance: 5%; Vendor: Digikey; Vendor P/N: RHM0.0GCT-ND; Volts/Amps/Watts: 0.1W
R208 R217 = RES0603_3: RES, 0603 OPTION; Label: OPT 0; Manufacturer: Rohm; Manufacturer P/N: RHM0.0GCT-ND; Part Number: OPTION; Tolerance: 5%; Vendor: Digikey; Vendor P/N: RHM0.0GCT-ND; Volts/Amps/Watts: 0.1W
R210 = RES0603_11: RES, 0603 10K OHMS 5% 1/10W; Part Number: VISHAY CRCW060310K0JNEA
R211 = RES0603_0: RES, 0603 0 OHMS JUMPER; Manufacturer: Rohm; Manufacturer P/N: RHM0.0GCT-ND; Part Number: VISHAY CRCW06030000Z0EA; Tolerance: 5%; Vendor: Digikey; Vendor P/N: RHM0.0GCT-ND; Volts/Amps/Watts: 0.1W
R213 R223 = RES0603_0: RES, 0603 4.99K OHMS 1% 1/10W; Manufacturer: ROHM; Manufacturer P/N: MCR03EZPFX4991; Part Number: VISHAY CRCW06034K99FKEA; Vendor: Digikey; Vendor P/N: RHM4.99KHCT-ND; Volts/Amps/Watts: 0.1w
R215 R222 = RES0603_0: RES, 0603 0 OHMS JUMPER; Label: OPT 0; Manufacturer: Rohm; Manufacturer P/N: RHM0.0GCT-ND; Part Number: VISHAY CRCW06030000Z0EA; Tolerance: 5%; Vendor: Digikey; Vendor P/N: RHM0.0GCT-ND; Volts/Amps/Watts: 0.1W
R216 R218 R219 R221 = RES0603_0: RES, 0603 OPTION; Label: OPT 0; Manufacturer: Rohm; Manufacturer P/N: RHM0.0GCT-ND; Part Number: OPTION; Tolerance: 5%; Vendor: Digikey; Vendor P/N: RHM0.0GCT-ND; Volts/Amps/Watts: 0.1W
R220 = RES0603_11: RES, 0603 15.8K OHMS 1% 1/10W; Part Number: VISHAY CRCW060315K8FKEA
U5 = 24LC025-I_SN: IC, 24LC05-I/ST; Part Number: MICROCHIP 24LC025-I/ST

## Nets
3V3: J23.5(LGKPWR) Q1.2(S) Q4.3(D) R124.1 R221.1 R224.1
+5V: C64.1 C68.1 R123.1 R202.2 R227.2 U6.1(OUTPUT)
GND_POWER: C31.2 C32.2 C33.2 C35.2 C40.2 C43.2 C45.2 C47.2 C50.2 C52.2 C54.2 C57.2 C64.2 C65.2 C66.2 C70.1 C71.2 C73.2 CIN1.2 CIN2.2 CIN3.2 CIN4.2 CIN5.2 CIN6.2 CIN7.2 CIN8.2 CIN9.2 CIN10.2 CIN11.2 CIN12.2 CIN13.2 CIN14.2 CIN15.2 CIN16.2 CIN17.2 CIN18.2 CIN19.2 CIN20.2 CIN21.2 CIN22.2 CIN23.2 CIN24.2 CIN26.2 CIN27.2 CIN28.2 CIN29.2 CIN30.2 CIN31.2 CIN32.2 CIN34.2 CIN35.2 CIN36.2 CIN37.2 CIN38.2 COUT1.2 COUT2.2 COUT3.2 COUT4.2 COUT5.2 COUT6.2 COUT7.2 COUT8.2 COUT9.2 COUT10.2 COUT11.2 COUT12.2 COUT13.2 COUT14.2 COUT15.2 COUT16.2 COUT17.2 COUT18.2 COUT19.2 COUT20.2 COUT21.2 COUT22.2 COUT23.2 COUT24.2 COUT25.2 COUT26.2 COUT27.2 COUT28.2 COUT29.2 COUT30.2 COUT31.2 COUT32.2 COUT33.2 COUT34.2 COUT35.2 COUT36.2 COUT37.2 COUT38.2 COUT39.2 COUT40.2 COUT41.2 COUT42.2 COUT43.2 COUT44.2 COUT45.2 COUT46.2 COUT47.2 COUT48.2 COUT49.2 COUT50.2 COUT51.2 COUT52.2 COUT53.2 COUT54.2 COUT55.2 COUT56.2 COUT57.2 COUT58.2 COUT59.2 COUT60.2 COUT61.2 COUT62.2 COUT63.2 COUT64.2 COUT65.2 COUT66.2 COUT67.2 COUT68.2 COUT69.2 COUT70.2 COUT71.2 COUT72.2 COUT73.2 COUT74.2 COUT75.2 COUT76.2 COUT77.2 COUT78.2 COUT79.2 COUT80.2 COUT81.2 COUT82.2 COUT83.2 COUT84.2 COUT85.2 COUT86.2 COUT87.2 COUT88.2 COUT89.2 COUT90.2 COUT91.2 COUT92.2 COUT93.2 COUT94.2 COUT95.2 COUT96.2 COUT97.2 COUT98.2 COUT99.2 COUT100.2 COUT101.2 COUT102.2 E2.1(TP) E5.1(TP) E14.1(TP) E23.1(TP) E24.1(TP) J2.1(TP) J5.1(TP) J8.1(TP) J15.2 J15.3 J15.4 J15.5 J17.11(GND) J17.12(GND) J18.1(TP) J20.1(TP) J21.2 J21.3 J21.4 J21.5 J22.11(GND) J22.12(GND) J23.3(GND) J23.10(GND) J24.2(GND) JP4.1 R32.2 R116.2 R118.1 R220.2 R226.2 R230.1 R231.1 R232.1 U1.A3(GND) U1.A4(GND) U1.A5(GND) U1.A9(GND) U1.A10(GND) U1.A11(GND) U1.AA3(GND) U1.AA4(GND) U1.AA5(GND) U1.AA9(GND) U1.AA10(GND) U1.AA11(GND) U1.AB3(GND) U1.AB4(GND) U1.AB5(GND) U1.AB9(GND) U1.AB10(GND) U1.AB11(GND) U1.B3(GND) U1.B4(GND) U1.B5(GND) U1.B9(GND) U1.B10(GND) U1.B11(GND) U1.C3(GND) U1.C4(GND) U1.C5(GND) U1.C9(GND) U1.C10(GND) U1.C11(GND) U1.D3(GND) U1.D4(GND) U1.D5(GND) U1.D9(GND) U1.D10(GND) U1.D11(GND) U1.E3(GND) U1.E4(GND) U1.E5(GND) U1.E9(GND) U1.E10(GND) U1.E11(GND) U1.F3(GND) U1.F4(GND) U1.F5(GND) U1.F9(GND) U1.F10(GND) U1.F11(GND) U1.G3(GND) U1.G4(GND) U1.G5(GND) U1.G9(GND) U1.G11(GND) U1.G12(GND) U1.G13(GND) U1.H3(GND) U1.H4(GND) U1.H5(GND) U1.J3(GND) U1.J4(GND) U1.J5(GND) U1.K3(GND) U1.K4(GND) U1.K5(GND) U1.K10(GND) U1.K11(GND) U1.L1(GND) U1.L2(GND) U1.L3(GND) U1.L4(GND) U1.L5(GND) U1.L6(GND) U1.L7(GND) U1.L14(GND) U1.L15(GND) U1.M1(GND) U1.M2(GND) U1.M3(GND) U1.M4(GND) U1.M5(GND) U1.M6(GND) U1.M7(GND) U1.M14(GND) U1.M15(GND) U1.N3(GND) U1.N4(GND) U1.N5(GND) U1.N8(GND) U1.N10(GND) U1.N11(GND) U1.N12(GND) U1.P3(GND) U1.P4(GND) U1.P5(GND) U1.P8(GND) U1.P9(GND) U1.P10(GND) U1.P11(GND) U1.P12(GND) U1.R3(GND) U1.R4(GND) U1.R5(GND) U1.R9(GND) U1.R11(GND) U1.R12(GND) U1.T3(GND) U1.T4(GND) U1.T5(GND) U1.T9(GND) U1.T10(GND) U1.T12(GND) U1.T13(GND) U1.U3(GND) U1.U4(GND) U1.U5(GND) U1.U9(GND) U1.U10(GND) U1.U11(GND) U1.V3(GND) U1.V4(GND) U1.V5(GND) U1.V10(GND) U1.V11(GND) U1.W3(GND) U1.W4(GND) U1.W5(GND) U1.W9(GND) U1.W10(GND) U1.W11(GND) U1.Y3(GND) U1.Y4(GND) U1.Y5(GND) U1.Y9(GND) U1.Y11(GND) U2.A3(GND) U2.A4(GND) U2.A5(GND) U2.A9(GND) U2.A10(GND) U2.A11(GND) U2.AA3(GND) U2.AA4(GND) U2.AA5(GND) U2.AA9(GND) U2.AA10(GND) U2.AA11(GND) U2.AB3(GND) U2.AB4(GND) U2.AB5(GND) U2.AB9(GND) U2.AB10(GND) U2.AB11(GND) U2.B3(GND) U2.B4(GND) U2.B5(GND) U2.B9(GND) U2.B10(GND) U2.B11(GND) U2.C3(GND) U2.C4(GND) U2.C5(GND) U2.C9(GND) U2.C10(GND) U2.C11(GND) U2.D3(GND) U2.D4(GND) U2.D5(GND) U2.D9(GND) U2.D10(GND) U2.D11(GND) U2.E3(GND) U2.E4(GND) U2.E5(GND) U2.E9(GND) U2.E10(GND) U2.E11(GND) U2.F3(GND) U2.F4(GND) U2.F5(GND) U2.F9(GND) U2.F10(GND) U2.F11(GND) U2.G3(GND) U2.G4(GND) U2.G5(GND) U2.G9(GND) U2.G11(GND) U2.G12(GND) U2.G13(GND) U2.H3(GND) U2.H4(GND) U2.H5(GND) U2.J3(GND) U2.J4(GND) U2.J5(GND) U2.K3(GND) U2.K4(GND) U2.K5(GND) U2.K10(GND) U2.K11(GND) U2.L1(GND) U2.L2(GND) U2.L3(GND) U2.L4(GND) U2.L5(GND) U2.L6(GND) U2.L7(GND) U2.L14(GND) U2.L15(GND) U2.M1(GND) U2.M2(GND) U2.M3(GND) U2.M4(GND) U2.M5(GND) U2.M6(GND) U2.M7(GND) U2.M14(GND) U2.M15(GND) U2.N3(GND) U2.N4(GND) U2.N5(GND) U2.N8(GND) U2.N10(GND) U2.N11(GND) U2.N12(GND) U2.P3(GND) U2.P4(GND) U2.P5(GND) U2.P8(GND) U2.P9(GND) U2.P10(GND) U2.P11(GND) U2.P12(GND) U2.R3(GND) U2.R4(GND) U2.R5(GND) U2.R9(GND) U2.R11(GND) U2.R12(GND) U2.T3(GND) U2.T4(GND) U2.T5(GND) U2.T9(GND) U2.T10(GND) U2.T12(GND) U2.T13(GND) U2.U3(GND) U2.U4(GND) U2.U5(GND) U2.U9(GND) U2.U10(GND) U2.U11(GND) U2.V3(GND) U2.V4(GND) U2.V5(GND) U2.V10(GND) U2.V11(GND) U2.W3(GND) U2.W4(GND) U2.W5(GND) U2.W9(GND) U2.W10(GND) U2.W11(GND) U2.Y3(GND) U2.Y4(GND) U2.Y5(GND) U2.Y9(GND) U2.Y11(GND) U3.A3(GND) U3.A4(GND) U3.A5(GND) U3.A9(GND) U3.A10(GND) U3.A11(GND) U3.AA3(GND) U3.AA4(GND) U3.AA5(GND) U3.AA9(GND) U3.AA10(GND) U3.AA11(GND) U3.AB3(GND) U3.AB4(GND) U3.AB5(GND) U3.AB9(GND) U3.AB10(GND) U3.AB11(GND) U3.B3(GND) U3.B4(GND) U3.B5(GND) U3.B9(GND) U3.B10(GND) U3.B11(GND) U3.C3(GND) U3.C4(GND) U3.C5(GND) U3.C9(GND) U3.C10(GND) U3.C11(GND) U3.D3(GND) U3.D4(GND) U3.D5(GND) U3.D9(GND) U3.D10(GND) U3.D11(GND) U3.E3(GND) U3.E4(GND) U3.E5(GND) U3.E9(GND) U3.E10(GND) U3.E11(GND) U3.F3(GND) U3.F4(GND) U3.F5(GND) U3.F9(GND) U3.F10(GND) U3.F11(GND) U3.G3(GND) U3.G4(GND) U3.G5(GND) U3.G9(GND) U3.G11(GND) U3.G12(GND) U3.G13(GND) U3.H3(GND) U3.H4(GND) U3.H5(GND) U3.J3(GND) U3.J4(GND) U3.J5(GND) U3.K3(GND) U3.K4(GND) U3.K5(GND) U3.K10(GND) U3.K11(GND) U3.L1(GND) U3.L2(GND) U3.L3(GND) U3.L4(GND) U3.L5(GND) U3.L6(GND) U3.L7(GND) U3.L14(GND) U3.L15(GND) U3.M1(GND) U3.M2(GND) U3.M3(GND) U3.M4(GND) U3.M5(GND) U3.M6(GND) U3.M7(GND) U3.M14(GND) U3.M15(GND) U3.N3(GND) U3.N4(GND) U3.N5(GND) U3.N8(GND) U3.N10(GND) U3.N11(GND) U3.N12(GND) U3.P3(GND) U3.P4(GND) U3.P5(GND) U3.P8(GND) U3.P9(GND) U3.P10(GND) U3.P11(GND) U3.P12(GND) U3.R3(GND) U3.R4(GND) U3.R5(GND) U3.R9(GND) U3.R11(GND) U3.R12(GND) U3.T3(GND) U3.T4(GND) U3.T5(GND) U3.T9(GND) U3.T10(GND) U3.T12(GND) U3.T13(GND) U3.U3(GND) U3.U4(GND) U3.U5(GND) U3.U9(GND) U3.U10(GND) U3.U11(GND) U3.V3(GND) U3.V4(GND) U3.V5(GND) U3.V10(GND) U3.V11(GND) U3.W3(GND) U3.W4(GND) U3.W5(GND) U3.W9(GND) U3.W10(GND) U3.W11(GND) U3.Y3(GND) U3.Y4(GND) U3.Y5(GND) U3.Y9(GND) U3.Y11(GND) U4.A3(GND) U4.A4(GND) U4.A5(GND) U4.A9(GND) U4.A10(GND) U4.A11(GND) U4.AA3(GND) U4.AA4(GND) U4.AA5(GND) U4.AA9(GND) U4.AA10(GND) U4.AA11(GND) U4.AB3(GND) U4.AB4(GND) U4.AB5(GND) U4.AB9(GND) U4.AB10(GND) U4.AB11(GND) U4.B3(GND) U4.B4(GND) U4.B5(GND) U4.B9(GND) U4.B10(GND) U4.B11(GND) U4.C3(GND) U4.C4(GND) U4.C5(GND) U4.C9(GND) U4.C10(GND) U4.C11(GND) U4.D3(GND) U4.D4(GND) U4.D5(GND) U4.D9(GND) U4.D10(GND) U4.D11(GND) U4.E3(GND) U4.E4(GND) U4.E5(GND) U4.E9(GND) U4.E10(GND) U4.E11(GND) U4.F3(GND) U4.F4(GND) U4.F5(GND) U4.F9(GND) U4.F10(GND) U4.F11(GND) U4.G3(GND) U4.G4(GND) U4.G5(GND) U4.G9(GND) U4.G11(GND) U4.G12(GND) U4.G13(GND) U4.H3(GND) U4.H4(GND) U4.H5(GND) U4.J3(GND) U4.J4(GND) U4.J5(GND) U4.K3(GND) U4.K4(GND) U4.K5(GND) U4.K10(GND) U4.K11(GND) U4.L1(GND) U4.L2(GND) U4.L3(GND) U4.L4(GND) U4.L5(GND) U4.L6(GND) U4.L7(GND) U4.L14(GND) U4.L15(GND) U4.M1(GND) U4.M2(GND) U4.M3(GND) U4.M4(GND) U4.M5(GND) U4.M6(GND) U4.M7(GND) U4.M14(GND) U4.M15(GND) U4.N3(GND) U4.N4(GND) U4.N5(GND) U4.N8(GND) U4.N10(GND) U4.N11(GND) U4.N12(GND) U4.P3(GND) U4.P4(GND) U4.P5(GND) U4.P8(GND) U4.P9(GND) U4.P10(GND) U4.P11(GND) U4.P12(GND) U4.R3(GND) U4.R4(GND) U4.R5(GND) U4.R9(GND) U4.R11(GND) U4.R12(GND) U4.T3(GND) U4.T4(GND) U4.T5(GND) U4.T9(GND) U4.T10(GND) U4.T12(GND) U4.T13(GND) U4.U3(GND) U4.U4(GND) U4.U5(GND) U4.U9(GND) U4.U10(GND) U4.U11(GND) U4.V3(GND) U4.V4(GND) U4.V5(GND) U4.V10(GND) U4.V11(GND) U4.W3(GND) U4.W4(GND) U4.W5(GND) U4.W9(GND) U4.W10(GND) U4.W11(GND) U4.Y3(GND) U4.Y4(GND) U4.Y5(GND) U4.Y9(GND) U4.Y11(GND) U5.1(A0) U5.2(A1) U5.3(A2) U5.4(VSS) U5.7(WP) U6.3(GND) U6.6(GND) U6.7(GND)
GND_SIGNAL: C14.2 C15.2 C28.2 C34.1 C36.1 C46.1 C58.1 C67.2 C68.2 C74.2 E18.1(TP) E21.1(TP) Q5.2(S) Q6.2(S) R24.1 R26.1 R27.1 R28.1 R29.1 R30.1 R31.1 R86.2 R110.1 R110.2 R113.1 R115.2 R117.1 R120.1 R121.1 R126.1 R127.1 R130.1 R137.1 R138.1 R139.1 R140.1 R142.1 R144.1 R145.1 R148.1 R150.1 R151.1 R152.1 R154.1 R155.1 R157.1 R203.2 R234.2 SW1.3 SW2.3 U1.L10(SGND) U1.L11(SGND) U1.L12(SGND) U1.M10(SGND) U1.M11(SGND) U1.M12(SGND) U2.L10(SGND) U2.L11(SGND) U2.L12(SGND) U2.M10(SGND) U2.M11(SGND) U2.M12(SGND) U3.L10(SGND) U3.L11(SGND) U3.L12(SGND) U3.M10(SGND) U3.M11(SGND) U3.M12(SGND) U4.L10(SGND) U4.L11(SGND) U4.L12(SGND) U4.M10(SGND) U4.M11(SGND) U4.M12(SGND) U7.2(GND) U8.2(V-)
SVIN: R8.1 R9.2 R238.1 R239.2 U1.V9(SVIN)
SVIN2: R109.1 R132.2 R240.1 R241.2 U2.V9(SVIN)
SVIN3: R134.1 R146.2 R242.1 R243.2 U3.V9(SVIN)
SVIN4: R158.2 R160.1 R244.2 R245.1 U4.V9(SVIN)
VCC: E26.1(TP) R239.1 R241.1 R243.1 R244.1
VDD25: E16.1(TP) U1.G10(VDD25)
VDD33: D3.1(CATHODE) E8.1(TP) Q4.2(S) R10.1 R11.1 R12.1 R13.1 R14.1 R15.1 R18.1 R94.1 R106.1 U1.K9(VDD33)
VIN: C65.1 CIN1.1 CIN16.1 CIN37.1 CIN38.1 E4.1(TP) J1.1(TP) R9.1 R90.1 R91.1 R108.1 R112.1 R132.1 R133.1 R135.1 R146.1 R147.1 R158.1 R159.1 R210.1 R217.1 R229.1 U6.8(VIN)
VIN1: CIN2.1 CIN3.1 CIN4.1 CIN5.1 CIN6.1 CIN7.1 CIN8.1 CIN9.1 R90.2 R92.1 U1.A6(VIN1) U1.A7(VIN1) U1.A8(VIN1) U1.AA6(VIN0) U1.AA7(VIN0) U1.AA8(VIN0) U1.AB6(VIN0) U1.AB7(VIN0) U1.AB8(VIN0) U1.B6(VIN1) U1.B7(VIN1) U1.B8(VIN1) U1.C6(VIN1) U1.C7(VIN1) U1.C8(VIN1) U1.D6(VIN1) U1.D7(VIN1) U1.D8(VIN1) U1.E6(VIN1) U1.E7(VIN1) U1.E8(VIN1) U1.F6(VIN1) U1.F7(VIN1) U1.F8(VIN1) U1.G6(VIN1) U1.G7(VIN1) U1.G8(VIN1) U1.H6(VIN1) U1.H7(VIN1) U1.H8(VIN1) U1.J6(VIN1) U1.J7(VIN1) U1.K6(VIN1) U1.K7(VIN1) U1.N6(VIN0) U1.N7(VIN0) U1.P6(VIN0) U1.P7(VIN0) U1.R6(VIN0) U1.R7(VIN0) U1.R8(VIN0) U1.T6(VIN0) U1.T7(VIN0) U1.T8(VIN0) U1.U6(VIN0) U1.U7(VIN0) U1.U8(VIN0) U1.V6(VIN0) U1.V7(VIN0) U1.V8(VIN0) U1.W6(VIN0) U1.W7(VIN0) U1.W8(VIN0) U1.Y6(VIN0) U1.Y7(VIN0) U1.Y8(VIN0)
VIN2: CIN10.1 CIN11.1 CIN12.1 CIN13.1 CIN14.1 CIN15.1 CIN17.1 CIN18.1 R108.2 R114.1 U2.A6(VIN1) U2.A7(VIN1) U2.A8(VIN1) U2.AA6(VIN0) U2.AA7(VIN0) U2.AA8(VIN0) U2.AB6(VIN0) U2.AB7(VIN0) U2.AB8(VIN0) U2.B6(VIN1) U2.B7(VIN1) U2.B8(VIN1) U2.C6(VIN1) U2.C7(VIN1) U2.C8(VIN1) U2.D6(VIN1) U2.D7(VIN1) U2.D8(VIN1) U2.E6(VIN1) U2.E7(VIN1) U2.E8(VIN1) U2.F6(VIN1) U2.F7(VIN1) U2.F8(VIN1) U2.G6(VIN1) U2.G7(VIN1) U2.G8(VIN1) U2.H6(VIN1) U2.H7(VIN1) U2.H8(VIN1) U2.J6(VIN1) U2.J7(VIN1) U2.K6(VIN1) U2.K7(VIN1) U2.N6(VIN0) U2.N7(VIN0) U2.P6(VIN0) U2.P7(VIN0) U2.R6(VIN0) U2.R7(VIN0) U2.R8(VIN0) U2.T6(VIN0) U2.T7(VIN0) U2.T8(VIN0) U2.U6(VIN0) U2.U7(VIN0) U2.U8(VIN0) U2.V6(VIN0) U2.V7(VIN0) U2.V8(VIN0) U2.W6(VIN0) U2.W7(VIN0) U2.W8(VIN0) U2.Y6(VIN0) U2.Y7(VIN0) U2.Y8(VIN0)
VIN3: CIN19.1 CIN20.1 CIN21.1 CIN22.1 CIN23.1 CIN24.1 CIN26.1 CIN27.1 R133.2 R136.1 U3.A6(VIN1) U3.A7(VIN1) U3.A8(VIN1) U3.AA6(VIN0) U3.AA7(VIN0) U3.AA8(VIN0) U3.AB6(VIN0) U3.AB7(VIN0) U3.AB8(VIN0) U3.B6(VIN1) U3.B7(VIN1) U3.B8(VIN1) U3.C6(VIN1) U3.C7(VIN1) U3.C8(VIN1) U3.D6(VIN1) U3.D7(VIN1) U3.D8(VIN1) U3.E6(VIN1) U3.E7(VIN1) U3.E8(VIN1) U3.F6(VIN1) U3.F7(VIN1) U3.F8(VIN1) U3.G6(VIN1) U3.G7(VIN1) U3.G8(VIN1) U3.H6(VIN1) U3.H7(VIN1) U3.H8(VIN1) U3.J6(VIN1) U3.J7(VIN1) U3.K6(VIN1) U3.K7(VIN1) U3.N6(VIN0) U3.N7(VIN0) U3.P6(VIN0) U3.P7(VIN0) U3.R6(VIN0) U3.R7(VIN0) U3.R8(VIN0) U3.T6(VIN0) U3.T7(VIN0) U3.T8(VIN0) U3.U6(VIN0) U3.U7(VIN0) U3.U8(VIN0) U3.V6(VIN0) U3.V7(VIN0) U3.V8(VIN0) U3.W6(VIN0) U3.W7(VIN0) U3.W8(VIN0) U3.Y6(VIN0) U3.Y7(VIN0) U3.Y8(VIN0)
VIN4: CIN28.1 CIN29.1 CIN30.1 CIN31.1 CIN32.1 CIN34.1 CIN35.1 CIN36.1 R149.1 R159.2 U4.A6(VIN1) U4.A7(VIN1) U4.A8(VIN1) U4.AA6(VIN0) U4.AA7(VIN0) U4.AA8(VIN0) U4.AB6(VIN0) U4.AB7(VIN0) U4.AB8(VIN0) U4.B6(VIN1) U4.B7(VIN1) U4.B8(VIN1) U4.C6(VIN1) U4.C7(VIN1) U4.C8(VIN1) U4.D6(VIN1) U4.D7(VIN1) U4.D8(VIN1) U4.E6(VIN1) U4.E7(VIN1) U4.E8(VIN1) U4.F6(VIN1) U4.F7(VIN1) U4.F8(VIN1) U4.G6(VIN1) U4.G7(VIN1) U4.G8(VIN1) U4.H6(VIN1) U4.H7(VIN1) U4.H8(VIN1) U4.J6(VIN1) U4.J7(VIN1) U4.K6(VIN1) U4.K7(VIN1) U4.N6(VIN0) U4.N7(VIN0) U4.P6(VIN0) U4.P7(VIN0) U4.R6(VIN0) U4.R7(VIN0) U4.R8(VIN0) U4.T6(VIN0) U4.T7(VIN0) U4.T8(VIN0) U4.U6(VIN0) U4.U7(VIN0) U4.U8(VIN0) U4.V6(VIN0) U4.V7(VIN0) U4.V8(VIN0) U4.W6(VIN0) U4.W7(VIN0) U4.W8(VIN0) U4.Y6(VIN0) U4.Y7(VIN0) U4.Y8(VIN0)
ALERTB: E10.1(TP) J17.3(ALERTB) J22.3(ALERTB) J23.6(ALERTB) Q1.1(G) R12.2 U1.J13(~{ALERT}) U2.J13(~{ALERT}) U3.J13(~{ALERT}) U4.J13(~{ALERT})
AUX3V4: D3.2(ANODE) J24.4(AUX3V4)
AUXVCC: C71.1 E19.1(A) J17.8(AUXP) J22.8(AUXP) J23.1(AUXP) R213.1 R223.1 U5.8(VCC)
COMP0a: C15.1 U1.L8(COMP1a) U1.N13(COMP0a) U2.L8(COMP1a) U2.N13(COMP0a) U3.L8(COMP1a) U3.N13(COMP0a) U4.L8(COMP1a) U4.N13(COMP0a)
COMP0b: C14.1 U1.L9(COMP1b) U1.M13(COMP0b) U2.L9(COMP1b) U2.M13(COMP0b) U3.L9(COMP1b) U3.M13(COMP0b) U4.L9(COMP1b) U4.M13(COMP0b)
EESCL: J23.11(AUXSCL) R213.2 U5.6(SCL)
EESDA: J23.12(AUXSDA) R223.2 U5.5(SDA)
FAULT0: D2.2(ANODE) E13.1(TP) Q5.1(G) R15.2 R215.2 U1.H12(~{FAULT1}) U1.H13(~{FAULT0}) U2.H12(~{FAULT1}) U2.H13(~{FAULT0}) U3.H12(~{FAULT1}) U3.H13(~{FAULT0}) U4.H12(~{FAULT1}) U4.H13(~{FAULT0})
INTVCC: C34.2 E3.1(TP) R8.2 U1.R10(INTVCC)
INTVCC2: C36.2 R109.2 U2.R10(INTVCC)
INTVCC3: C46.2 R134.2 U3.R10(INTVCC)
INTVCC4: C58.2 R160.2 U4.R10(INTVCC)
PGOOD0: E25.1(TP) Q6.1(G) R18.2 U1.N9(PGOOD1) U1.R14(PGOOD0) U2.N9(PGOOD1) U2.R14(PGOOD0) U3.N9(PGOOD1) U3.R14(PGOOD0) U4.N9(PGOOD1) U4.R14(PGOOD0)
RUN0: D2.1(CATHODE) E1.1(TP) R70.2 R94.2 R125.2 R218.2 R222.2 SW1.1 SW1.2 U1.J12(RUN0) U1.K12(RUN1) U2.J12(RUN0) U2.K12(RUN1) U3.J12(RUN0) U3.K12(RUN1) U4.J12(RUN0) U4.K12(RUN1)
RUNP: R106.2 R237.2 SW2.1 SW2.2 U1.Y10(RUNP) U2.Y10(RUNP) U3.Y10(RUNP) U4.Y10(RUNP)
SCL: E11.1(TP) J17.6(SCL) J22.6(SCL) J23.4(SCL) J24.3(SCL) R13.2 U1.J14(SCL) U2.J14(SCL) U3.J14(SCL) U4.J14(SCL)
SDA: E12.1(TP) J17.4(SDA) J22.4(SDA) J23.2(SDA) J24.1(SDA) R14.2 U1.H14(SDA) U2.H14(SDA) U3.H14(SDA) U4.H14(SDA)
SHARE_CLK: E6.1(TP) R11.2 R211.1 U1.K8(SHARE_CLK) U2.K8(SHARE_CLK) U3.K8(SHARE_CLK) U4.K8(SHARE_CLK)
SYNC: E9.1(TP) R10.2 R219.1 U1.K14(SYNC) U2.K14(SYNC) U3.K14(SYNC) U4.K14(SYNC)
VBIAS: C33.1 E20.1(TP) U1.T11(VBIAS)
VBIAS2: C35.1 U2.T11(VBIAS)
VBIAS3: C45.1 U3.T11(VBIAS)
VBIAS4: C57.1 U4.T11(VBIAS)
VOSNS0+: C16.1 C17.1 C41.1 C44.1 C48.1 C51.1 C53.1 C56.1 E15.1(TP) R25.1 U1.M9(VOSNS1+) U1.P14(VOSNS0+) U2.M9(VOSNS1+) U2.P14(VOSNS0+) U3.M9(VOSNS1+) U3.P14(VOSNS0+) U4.M9(VOSNS1+) U4.P14(VOSNS0+)
VOSNS0-: C16.2 C17.2 C41.2 C44.2 C48.2 C51.2 C53.2 C56.2 E17.1(TP) R32.1 U1.M8(VOSNS1-) U1.N14(VOSNS0-) U2.M8(VOSNS1-) U2.N14(VOSNS0-) U3.M8(VOSNS1-) U3.N14(VOSNS0-) U4.M8(VOSNS1-) U4.N14(VOSNS0-)
VOUT: C66.1 COUT1.1 COUT2.1 COUT3.1 COUT4.1 COUT5.1 COUT6.1 COUT7.1 COUT8.1 COUT9.1 COUT10.1 COUT11.1 COUT12.1 COUT13.1 COUT14.1 COUT15.1 COUT16.1 COUT17.1 COUT18.1 COUT19.1 COUT20.1 COUT21.1 COUT22.1 COUT23.1 COUT24.1 COUT25.1 COUT26.1 COUT27.1 COUT28.1 COUT29.1 COUT30.1 COUT31.1 COUT32.1 COUT33.1 COUT34.1 COUT35.1 COUT36.1 COUT37.1 COUT38.1 COUT39.1 COUT40.1 COUT41.1 COUT42.1 COUT43.1 COUT44.1 COUT45.1 COUT46.1 COUT47.1 COUT48.1 COUT49.1 COUT50.1 COUT51.1 COUT52.1 COUT53.1 COUT54.1 COUT55.1 COUT56.1 COUT57.1 COUT58.1 COUT59.1 COUT60.1 COUT61.1 COUT62.1 COUT63.1 COUT64.1 COUT65.1 COUT66.1 COUT67.1 COUT68.1 COUT69.1 COUT70.1 COUT71.1 COUT72.1 COUT73.1 COUT74.1 COUT75.1 COUT76.1 COUT77.1 COUT78.1 COUT79.1 COUT80.1 COUT81.1 COUT82.1 COUT83.1 COUT84.1 COUT85.1 COUT86.1 COUT87.1 COUT88.1 COUT89.1 COUT90.1 COUT91.1 COUT92.1 COUT93.1 COUT94.1 COUT95.1 COUT96.1 COUT97.1 COUT98.1 COUT99.1 COUT100.1 COUT101.1 COUT102.1 J6.1(TP) J7.1(TP) J15.1 J16.1(TP) J19.1(TP) Q2.3 Q3.3 R25.2 R230.2 R231.2 U1.A12(VOUT1) U1.A13(VOUT1) U1.A14(VOUT1) U1.A15(VOUT1) U1.AA12(VOUT0) U1.AA13(VOUT0) U1.AA14(VOUT0) U1.AA15(VOUT0) U1.AB12(VOUT0) U1.AB13(VOUT0) U1.AB14(VOUT0) U1.AB15(VOUT0) U1.B12(VOUT1) U1.B13(VOUT1) U1.B14(VOUT1) U1.B15(VOUT1) U1.C12(VOUT1) U1.C13(VOUT1) U1.C14(VOUT1) U1.C15(VOUT1) U1.D12(VOUT1) U1.D13(VOUT1) U1.D14(VOUT1) U1.D15(VOUT1) U1.E12(VOUT1) U1.E13(VOUT1) U1.E14(VOUT1) U1.E15(VOUT1) U1.F12(VOUT1) U1.F13(VOUT1) U1.F14(VOUT1) U1.F15(VOUT1) U1.G15(VOUT1) U1.H15(VOUT1) U1.J15(VOUT1) U1.K15(VOUT1) U1.N15(VOUT0) U1.P15(VOUT0) U1.R15(VOUT0) U1.T15(VOUT0) U1.U12(VOUT0) U1.U13(VOUT0) U1.U14(VOUT0) U1.U15(VOUT0) U1.V12(VOUT0) U1.V13(VOUT0) U1.V14(VOUT0) U1.V15(VOUT0) U1.W12(VOUT0) U1.W13(VOUT0) U1.W14(VOUT0) U1.W15(VOUT0) U1.Y12(VOUT0) U1.Y13(VOUT0) U1.Y14(VOUT0) U1.Y15(VOUT0) U2.A12(VOUT1) U2.A13(VOUT1) U2.A14(VOUT1) U2.A15(VOUT1) U2.AA12(VOUT0) U2.AA13(VOUT0) U2.AA14(VOUT0) U2.AA15(VOUT0) U2.AB12(VOUT0) U2.AB13(VOUT0) U2.AB14(VOUT0) U2.AB15(VOUT0) U2.B12(VOUT1) U2.B13(VOUT1) U2.B14(VOUT1) U2.B15(VOUT1) U2.C12(VOUT1) U2.C13(VOUT1) U2.C14(VOUT1) U2.C15(VOUT1) U2.D12(VOUT1) U2.D13(VOUT1) U2.D14(VOUT1) U2.D15(VOUT1) U2.E12(VOUT1) U2.E13(VOUT1) U2.E14(VOUT1) U2.E15(VOUT1) U2.F12(VOUT1) U2.F13(VOUT1) U2.F14(VOUT1) U2.F15(VOUT1) U2.G15(VOUT1) U2.H15(VOUT1) U2.J15(VOUT1) U2.K15(VOUT1) U2.N15(VOUT0) U2.P15(VOUT0) U2.R15(VOUT0) U2.T15(VOUT0) U2.U12(VOUT0) U2.U13(VOUT0) U2.U14(VOUT0) U2.U15(VOUT0) U2.V12(VOUT0) U2.V13(VOUT0) U2.V14(VOUT0) U2.V15(VOUT0) U2.W12(VOUT0) U2.W13(VOUT0) U2.W14(VOUT0) U2.W15(VOUT0) U2.Y12(VOUT0) U2.Y13(VOUT0) U2.Y14(VOUT0) U2.Y15(VOUT0) U3.A12(VOUT1) U3.A13(VOUT1) U3.A14(VOUT1) U3.A15(VOUT1) U3.AA12(VOUT0) U3.AA13(VOUT0) U3.AA14(VOUT0) U3.AA15(VOUT0) U3.AB12(VOUT0) U3.AB13(VOUT0) U3.AB14(VOUT0) U3.AB15(VOUT0) U3.B12(VOUT1) U3.B13(VOUT1) U3.B14(VOUT1) U3.B15(VOUT1) U3.C12(VOUT1) U3.C13(VOUT1) U3.C14(VOUT1) U3.C15(VOUT1) U3.D12(VOUT1) U3.D13(VOUT1) U3.D14(VOUT1) U3.D15(VOUT1) U3.E12(VOUT1) U3.E13(VOUT1) U3.E14(VOUT1) U3.E15(VOUT1) U3.F12(VOUT1) U3.F13(VOUT1) U3.F14(VOUT1) U3.F15(VOUT1) U3.G15(VOUT1) U3.H15(VOUT1) U3.J15(VOUT1) U3.K15(VOUT1) U3.N15(VOUT0) U3.P15(VOUT0) U3.R15(VOUT0) U3.T15(VOUT0) U3.U12(VOUT0) U3.U13(VOUT0) U3.U14(VOUT0) U3.U15(VOUT0) U3.V12(VOUT0) U3.V13(VOUT0) U3.V14(VOUT0) U3.V15(VOUT0) U3.W12(VOUT0) U3.W13(VOUT0) U3.W14(VOUT0) U3.W15(VOUT0) U3.Y12(VOUT0) U3.Y13(VOUT0) U3.Y14(VOUT0) U3.Y15(VOUT0) U4.A12(VOUT1) U4.A13(VOUT1) U4.A14(VOUT1) U4.A15(VOUT1) U4.AA12(VOUT0) U4.AA13(VOUT0) U4.AA14(VOUT0) U4.AA15(VOUT0) U4.AB12(VOUT0) U4.AB13(VOUT0) U4.AB14(VOUT0) U4.AB15(VOUT0) U4.B12(VOUT1) U4.B13(VOUT1) U4.B14(VOUT1) U4.B15(VOUT1) U4.C12(VOUT1) U4.C13(VOUT1) U4.C14(VOUT1) U4.C15(VOUT1) U4.D12(VOUT1) U4.D13(VOUT1) U4.D14(VOUT1) U4.D15(VOUT1) U4.E12(VOUT1) U4.E13(VOUT1) U4.E14(VOUT1) U4.E15(VOUT1) U4.F12(VOUT1) U4.F13(VOUT1) U4.F14(VOUT1) U4.F15(VOUT1) U4.G15(VOUT1) U4.H15(VOUT1) U4.J15(VOUT1) U4.K15(VOUT1) U4.N15(VOUT0) U4.P15(VOUT0) U4.R15(VOUT0) U4.T15(VOUT0) U4.U12(VOUT0) U4.U13(VOUT0) U4.U14(VOUT0) U4.U15(VOUT0) U4.V12(VOUT0) U4.V13(VOUT0) U4.V14(VOUT0) U4.V15(VOUT0) U4.W12(VOUT0) U4.W13(VOUT0) U4.W14(VOUT0) U4.W15(VOUT0) U4.Y12(VOUT0) U4.Y13(VOUT0) U4.Y14(VOUT0) U4.Y15(VOUT0)
N17166430: P1.1(TP) R105.2 U1.A1(SW1) U1.A2(SW1) U1.B1(SW1) U1.B2(SW1) U1.C1(SW1) U1.C2(SW1) U1.D1(SW1) U1.D2(SW1) U1.E1(SW1) U1.E2(SW1) U1.F1(SW1) U1.F2(SW1) U1.G1(SW1) U1.G2(SW1) U1.H1(SW1) U1.H2(SW1) U1.J1(SW1) U1.J2(SW1) U1.K1(SW1) U1.K2(SW1)
N17222714: R26.2 U1.H11(ASEL)
N17223298: R27.2 U1.J11(FSWPHCFG)
N17223884: R28.2 U1.H9(VTRIM1CFG)
N17224472: R29.2 U1.J9(VTRIM0CFG)
N17225062: R30.2 U1.J10(VOUT0CFG)
N17225654: R31.2 U1.H10(VOUT1CFG)
N18377354: U1.G14(TSNS1B) U1.L13(TSNS1A)
N18377395: U1.K13(TSNS0A) U1.T14(TSNS0B)
N18437001: P2.1(TP) R104.2 U1.AA1(SW0) U1.AA2(SW0) U1.AB1(SW0) U1.AB2(SW0) U1.N1(SW0) U1.N2(SW0) U1.P1(SW0) U1.P2(SW0) U1.R1(SW0) U1.R2(SW0) U1.T1(SW0) U1.T2(SW0) U1.U1(SW0) U1.U2(SW0) U1.V1(SW0) U1.V2(SW0) U1.W1(SW0) U1.W2(SW0) U1.Y1(SW0) U1.Y2(SW0)
N18440006: C29.1 R91.2 R238.2 U1.R13(IN+)
N18440037: C29.2 R92.2 U1.P13(IN-)
N18449385: R24.2 U1.J8(WP)
N18468612: C31.1 R104.1
N18469531: C32.1 R105.1
N18607454: P6.1(TP) U2.G10(VDD25)
N18607560: P5.1(TP) U2.K9(VDD33)
N18607671: P4.1(TP) R128.2 U2.A1(SW1) U2.A2(SW1) U2.B1(SW1) U2.B2(SW1) U2.C1(SW1) U2.C2(SW1) U2.D1(SW1) U2.D2(SW1) U2.E1(SW1) U2.E2(SW1) U2.F1(SW1) U2.F2(SW1) U2.G1(SW1) U2.G2(SW1) U2.H1(SW1) U2.H2(SW1) U2.J1(SW1) U2.J2(SW1) U2.K1(SW1) U2.K2(SW1)
N18607759: C42.1 R112.2 R240.2 U2.R13(IN+)
N18608113: R126.2 U2.J8(WP)
N18608390: P3.1(TP) R122.2 U2.AA1(SW0) U2.AA2(SW0) U2.AB1(SW0) U2.AB2(SW0) U2.N1(SW0) U2.N2(SW0) U2.P1(SW0) U2.P2(SW0) U2.R1(SW0) U2.R2(SW0) U2.T1(SW0) U2.T2(SW0) U2.U1(SW0) U2.U2(SW0) U2.V1(SW0) U2.V2(SW0) U2.W1(SW0) U2.W2(SW0) U2.Y1(SW0) U2.Y2(SW0)
N18608494: C42.2 R114.2 U2.P13(IN-)
N18608703: R113.2 U2.H11(ASEL)
N18608758: R120.2 U2.J11(FSWPHCFG)
N18608879: R127.2 U2.H9(VTRIM1CFG)
N18608914: R130.2 U2.J9(VTRIM0CFG)
N18609032: R121.2 U2.J10(VOUT0CFG)
N18609201: U2.G14(TSNS1B) U2.L13(TSNS1A)
N18609203: U2.K13(TSNS0A) U2.T14(TSNS0B)
N18609290: R117.2 U2.H10(VOUT1CFG)
N18609496: C40.1 R122.1
N18609698: C43.1 R128.1
N18625132: P8.1(TP) U3.G10(VDD25)
N18625219: P7.1(TP) U3.K9(VDD33)
N18625353: C49.1 R135.2 R242.2 U3.R13(IN+)
N18625707: R142.2 U3.J8(WP)
N18625918: P10.1(TP) R143.2 U3.A1(SW1) U3.A2(SW1) U3.B1(SW1) U3.B2(SW1) U3.C1(SW1) U3.C2(SW1) U3.D1(SW1) U3.D2(SW1) U3.E1(SW1) U3.E2(SW1) U3.F1(SW1) U3.F2(SW1) U3.G1(SW1) U3.G2(SW1) U3.H1(SW1) U3.H2(SW1) U3.J1(SW1) U3.J2(SW1) U3.K1(SW1) U3.K2(SW1)
N18626036: C49.2 R136.2 U3.P13(IN-)
N18626044: P9.1(TP) R141.2 U3.AA1(SW0) U3.AA2(SW0) U3.AB1(SW0) U3.AB2(SW0) U3.N1(SW0) U3.N2(SW0) U3.P1(SW0) U3.P2(SW0) U3.R1(SW0) U3.R2(SW0) U3.T1(SW0) U3.T2(SW0) U3.U1(SW0) U3.U2(SW0) U3.V1(SW0) U3.V2(SW0) U3.W1(SW0) U3.W2(SW0) U3.Y1(SW0) U3.Y2(SW0)
N18626190: R137.2 U3.H11(ASEL)
N18626240: R139.2 U3.J11(FSWPHCFG)
N18626326: R144.2 U3.H9(VTRIM1CFG)
N18626340: R145.2 U3.J9(VTRIM0CFG)
N18626409: R140.2 U3.J10(VOUT0CFG)
N18626509: U3.G14(TSNS1B) U3.L13(TSNS1A)
N18626511: U3.K13(TSNS0A) U3.T14(TSNS0B)
N18626561: R138.2 U3.H10(VOUT1CFG)
N18626696: C47.1 R141.1
N18626824: C50.1 R143.1
N18630025: U4.G14(TSNS1B) U4.L13(TSNS1A)
N18630027: U4.K13(TSNS0A) U4.T14(TSNS0B)
N18630085: R150.2 U4.H10(VOUT1CFG)
N18630210: P11.1(TP) R153.2 U4.AA1(SW0) U4.AA2(SW0) U4.AB1(SW0) U4.AB2(SW0) U4.N1(SW0) U4.N2(SW0) U4.P1(SW0) U4.P2(SW0) U4.R1(SW0) U4.R2(SW0) U4.T1(SW0) U4.T2(SW0) U4.U1(SW0) U4.U2(SW0) U4.V1(SW0) U4.V2(SW0) U4.W1(SW0) U4.W2(SW0) U4.Y1(SW0) U4.Y2(SW0)
N18630212: C52.1 R153.1
N18630348: C54.1 R156.1
N18630382: P12.1(TP) R156.2 U4.A1(SW1) U4.A2(SW1) U4.B1(SW1) U4.B2(SW1) U4.C1(SW1) U4.C2(SW1) U4.D1(SW1) U4.D2(SW1) U4.E1(SW1) U4.E2(SW1) U4.F1(SW1) U4.F2(SW1) U4.G1(SW1) U4.G2(SW1) U4.H1(SW1) U4.H2(SW1) U4.J1(SW1) U4.J2(SW1) U4.K1(SW1) U4.K2(SW1)
N18630782: P14.1(TP) U4.G10(VDD25)
N18630869: P13.1(TP) U4.K9(VDD33)
N18630995: C55.1 R147.2 R245.2 U4.R13(IN+)
N18631021: R154.2 U4.J8(WP)
N18631686: C55.2 R149.2 U4.P13(IN-)
N18631840: R148.2 U4.H11(ASEL)
N18631890: R151.2 U4.J11(FSWPHCFG)
N18631976: R155.2 U4.H9(VTRIM1CFG)
N18631990: R157.2 U4.J9(VTRIM0CFG)
N18632050: R152.2 U4.J10(VOUT0CFG)
N18647105: R226.1 R227.1 U6.2(SENSE/ADJ)
N18647137: JP2.1 R204.2
N18647141: JP2.2 JP2.3 Q2.1 Q3.1 R116.1 R236.2
N18647149: E7.1(TP) R236.1
N18647164: JP4.2 R229.2 U6.5(~{SHDN})
N18647274: C70.2 J21.1 Q2.2 Q3.2 R118.2 R205.2 R232.2
N18647294: R123.2 R203.1 U7.4(DIV)
N18647422: C67.1 R111.1 U7.6(OUT) U8.5(V+)
N18647490: R202.1 U7.5(V+)
N18647623: R110.3 R233.2 R234.1
N18647659: C69.1 R204.1 U8.1(VOUT)
N18647673: R111.2 R233.1 U8.3(+IN)
N18647675: C69.2 R205.1 U8.4(-IN)
N18647757: R115.1 R235.1 U7.1(MOD)
N18650245: C73.1 R125.1
N18650251: J23.8(OUTEN_0) R208.1
N18650277: Q4.1(G) R210.2 R220.1
N18650293: J17.2(CTRL) J22.2(CTRL) R208.2 R216.2 R222.1
N18650317: J17.9(UNUSED) J22.9(UNUSED) R218.1 R219.2
N18650319: J17.7(RESETB) J22.7(RESETB)
N18650321: J17.5(SHARE_CLK) J22.5(SHARE_CLK) R211.2
N18650335: J17.13(12V) J17.14(12V) J22.13(12V) J22.14(12V) R217.2
N18650367: J17.1(FAULTB) J22.1(FAULTB) R215.1
N18650393: J17.10(UNUSED) J22.10(UNUSED) R221.2
N18650930: D4.2(K) Q5.3(D)
N18650932: D4.1(A) R124.2
N18650942: D1.2(K) R86.1
N18650948: D1.1(A) Q1.3(D)
N18651180: J23.9(OUTEN_1) R216.1
N18651248: D5.2(K) Q6.3(D)
N18703972: R235.2 U7.3(SET)
N18772685: D5.1(A) R224.2
N18787304: C28.1 R70.1
N18789098: C74.1 R237.1

Not connected (* = marked no-connect by the designer): J23 7(GPIO_1); JP4 3; SW1 4 5 6; SW2 4 5 6; U6 4(NC)*

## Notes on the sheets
sheet 1
- ALL PARTS ON THIS PAGE ARE FOR DEMO ONLY, NOT NEEDED IN CUSTOMER DESIGN
- TO DC2086A
- TO DC1613A
- OPTIONAL CIRCUIT FOR PROGRAMMING
  WITHOUT VIN
- FAULT0
- PGOOD0
- ALERTB
- HIGH CURRENT POLYPHASE STEP-DOWN POWER uMODULE
  SUPPLY WITH DIGITAL POWER MANAGEMENT
- Monday, July 26, 2021
- SUPPLY WITH DIGITAL POWER SYSTEM MANAGEMENT
- SUPPLY WITH DIGITAL POWER MANAGEMENT
- SUPPLY WITH DIGITAL POWER SYSTEM MANAGEMENT
- SUPPLY WITH DIGITAL POWER SYSTEM MANAGEMENT
- DEMO CIRCUIT2784A(A,B,C)
- DEMO CIRCUIT2784A(A,B,C)
sheet 2
- ALL PARTS ON THIS PAGE ARE FOR DEMO ONLY, NOT NEEDED IN CUSTOMER DESIGN
- DYNAMIC LOAD CIRCUIT
- VOUT
- PULSE
- INT
- EXT
- 2512
- 2512
- 70Hz, 3% Duty Cycle
- OPT
- OPT
- 1%
- IOUT
- BLEEDER LOADS
- 1%
- BIAS
- ON
- OFF
- HIGH CURRENT POLYPHASE STEP-DOWN POWER uMODULE
  SUPPLY WITH DIGITAL POWER MANAGEMENT
- Monday, July 26, 2021
- 08-15-18
- HIGH CURRENT POLYPHASE STEP-DOWN POWER uMODULE
  SUPPLY WITH DIGITAL POWER MANAGEMENT
- HIGH CURRENT POLYPHASE STEP-DOWN POWER uMODULE
  SUPPLY WITH DIGITAL POWER MANAGEMENT
- SUPPLY WITH DIGITAL POWER SYSTEM MANAGEMENT
- SUPPLY WITH DIGITAL POWER MANAGEMENT
- SUPPLY WITH DIGITAL POWER SYSTEM MANAGEMENT
- SUPPLY WITH DIGITAL POWER SYSTEM MANAGEMENT
- Monday, July 26, 2021
- Monday, July 26, 2021
- DEMO CIRCUIT2784A(A,B,C)
- DEMO CIRCUIT2784A(A,B,C)
sheet 3
- 0.035 VIA
- TESTPOINTS
- HIGH CURRENT POLYPHASE STEP-DOWN POWER uMODULE
  SUPPLY WITH DIGITAL POWER MANAGEMENT
- Monday, July 26, 2021
sheet 4
- 0.035 VIA
- TESTPOINTS
- HIGH CURRENT POLYPHASE STEP-DOWN POWER uMODULE
  SUPPLY WITH DIGITAL POWER MANAGEMENT
- Monday, July 26, 2021
sheet 5
- 0.035 VIA
- TESTPOINTS
- HIGH CURRENT POLYPHASE STEP-DOWN POWER uMODULE
  SUPPLY WITH DIGITAL POWER MANAGEMENT
- Monday, July 26, 2021
sheet 6
- 0.035 VIA
- TESTPOINTS
- 4.5V - 16V
- RUN0
- ON
- OFF
- RUNP
- ON
- OFF
- 1.0V / UP TO 400A
- *
- ASSY
- U3
- U4
- C14
- C15
- COUT61,COUT59,COUT57,COUT70,COUT71,COUT72,COUT50,COUT56
- COUT73,COUT94,COUT92,COUT82,COUT83,COUT84,COUT86,COUT48
- CIN19,CIN20,CIN21,CIN22,
- CIN28,CIN29,CIN30,CIN31,
- COUT52,COUT58,COUT60,COUT62,
- COUT74,COUT75,COUT78,COUT80,
- COUT64,COUT67,COUT65,COUT55,COUT54,COUT53,COUT51,COUT49
- COUT76,COUT77,COUT79,COUT89,COUT91,COUT90,COUT85,COUT87
- CIN23,CIN24,CIN26,CIN27
- CIN32,CIN34,CIN35,CIN36
- COUT63,COUT66,COUT68,COUT69
- COUT81,COUT88,COUT95,COUT96
- -A
- OPT
- OPT
- OPT
- 15nF
- OPT
- OPT
- OPT
- OPT
- OPT
- OPT
- -B
- LTM4700
- OPT
- OPT
- 22nF
- 100uF
- OPT
- 22uF
- OPT
- 470uF
- OPT
- -C
- LTM4700
- LTM4700
- 560pF
- 10nF
- 100uF
- 100uF
- 22uF
- 22uF
- 470uF
- 470uF
- NOTE: UNLESS OTHERWISE SPECIFIED
- HIGH CURRENT POLYPHASE STEP-DOWN POWER uMODULE
  SUPPLY WITH DIGITAL POWER MANAGEMENT
- 1.  ALL RESISTORS AND CAP ARE 0603.
- 2.  WHEN VIN < 5.75V, CHANGE R8,R109,R134,R160 = 0 OHM
- Monday, July 26, 2021
